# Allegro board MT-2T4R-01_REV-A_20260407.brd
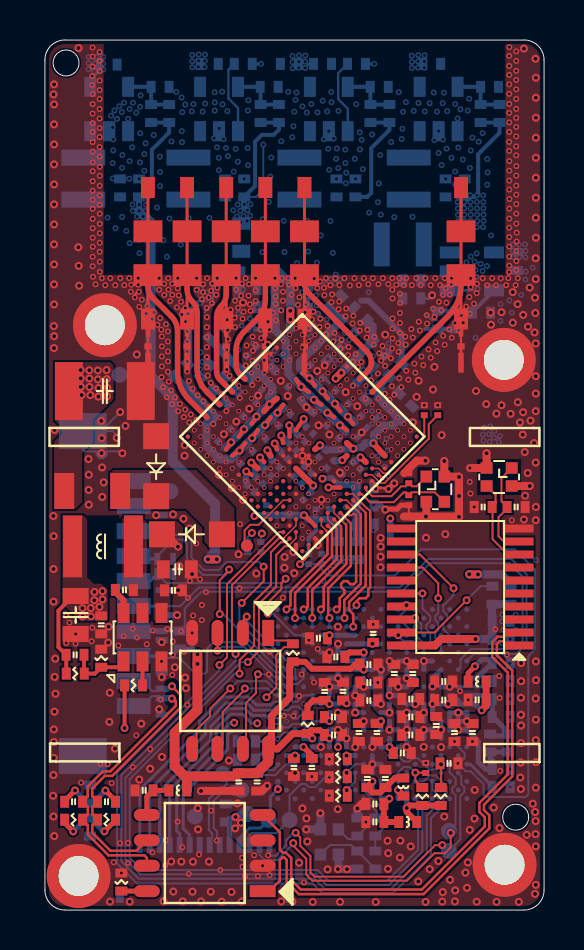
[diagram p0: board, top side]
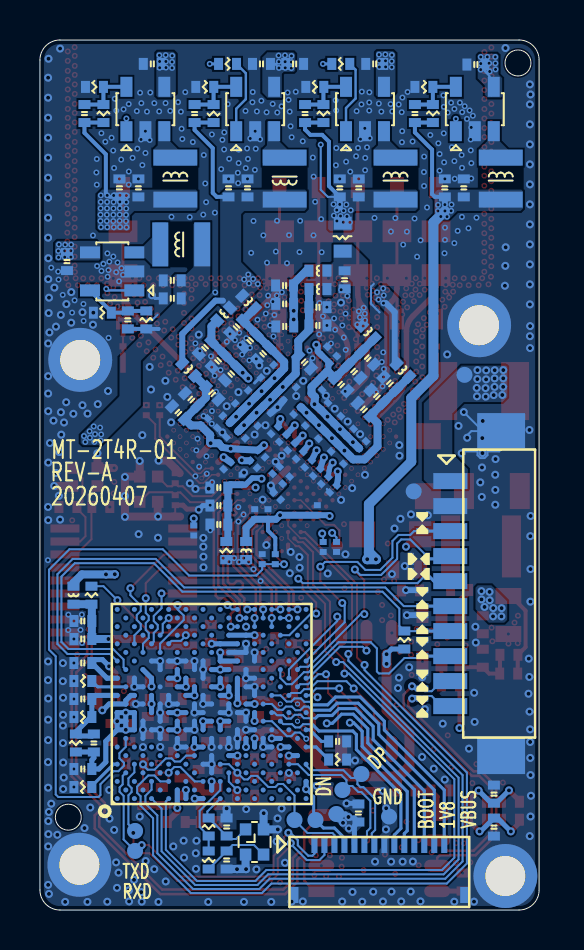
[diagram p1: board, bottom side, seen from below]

Outline 25 x 43.5 mm; copper layers: TOP, 02-GND1, 03-POWER, BOTTOM. Coordinates in mm from the lower left corner of the outline.
Outline path: circle c1.06,42.35 r0.65 ; circle c23.58,4.64 r0.65 ; 0,42.5 0,1 arc(0.29,0.29) 1,0 24,0 arc(24.71,0.29) 25,1 25,42.5 arc(24.71,43.21) 24,43.5 1,43.5 arc(0.29,43.21) 0,42.5

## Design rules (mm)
net group DP6: nets N2464554 N2465035
net group DP7: nets RXCAN TXCAN
net group DP8: nets CANH CANL
net group DP9: nets USB_DN USB_DP

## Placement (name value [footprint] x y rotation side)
C1  100pF  [0201]  13.12 27.08 225 bottom
C2  100pF  [0201]  14.39 25.81 225 bottom
C3  100pF  [0201]  13.76 26.45 225 bottom
C4  100pF  [0201]  15.05 25.16 225 bottom
C5  100pF  [0201]  15.67 24.54 225 bottom
C6  100pF  [0201]  12.34 26.3 45 bottom
C7  100pF  [0201]  12.98 25.67 45 bottom
C8  100pF  [0201]  13.62 25.03 45 bottom
C9  100pF  [0201]  14.27 24.38 45 bottom
C10  100pF  [0201]  14.89 23.76 45 bottom
C11  100pF  [0201]  11.53 24.4 135 bottom
C12  100pF  [0201]  12.12 24.96 135 bottom
C13  100pF  [0201]  9.62 22.49 135 bottom
C14  100pF  [0201]  10.88 23.74 135 bottom
C15  100pF  [0201]  10.24 23.1 135 bottom
C16  100pF  [0201]  11.04 25.83 315 bottom
C17  100pF  [0201]  10.75 25.19 315 bottom
C18  100pF  [0201]  10.1 24.52 315 bottom
C19  100pF  [0201]  9.46 23.88 315 bottom
C20  100pF  [0201]  8.84 23.26 315 bottom
C21  100pF  [0201]  10.31 27.52 315 bottom
C22  100pF  [0201]  10.79 27.99 315 bottom
C23  100pF  [0201]  11.14 21.89 135 bottom
C24  100pF  [0201]  11.99 22.73 135 bottom
C25  100pF  [0201]  12.84 23.58 135 bottom
C26  100pF  [0201]  10.31 21.05 135 bottom
C27  100pF  [0201]  17.3 18.98 90 bottom
C28  100pF  [0201]  15.62 22.21 135 bottom
C29  100pF  [0201]  11.57 22.31 135 bottom
C30  100pF  [0201]  12.41 23.16 135 bottom
C31  100pF  [0201]  14.3 22.29 45 bottom
C32  100pF  [0201]  13.24 23.99 135 bottom
C33  100pF  [0201]  10.73 21.48 135 bottom
C35  100pF  [0201]  15.84 23.47 315 bottom
C36  100pF  [0201]  13.9 22.81 45 bottom
C37  100pF  [0201]  16.77 24.4 315 bottom
C38  100pF  [0201]  16.3 23.93 315 bottom
C39  100pF  [0201]  14.87 21.51 270 bottom
C40  100pF  [0201]  13.17 21.99 315 bottom
C41  100pF  [0201]  12.67 21.49 315 bottom
C42  100pF  [0201]  13.12 20.69 45 bottom
C44  100pF  [0201]  14.24 19.79 270 bottom
C45  100pF  [0201]  11.11 19.99 270 bottom
C46  100pF  [0201]  13.58 19.79 270 bottom
C48  8pF  [0201]  18.23 21.59 270 top
C49  16pF  [0201]  18.23 20.49 90 top
C50  100pF  [0201]  19.67 24.99 270 top
C51  100nF  [0201]  13.87 17.54 270 bottom
C52  15pF  [C0402]  15.65 4.15 90 bottom
C53  15pF  [C0402]  15.65 2.5 270 bottom
C57  1uF  [C0402]  9.71 6.4 270 top
C66  10uF  [C0402]  11.08 30.14 0 bottom
C67  10nF  [C0402]  11.08 29.23 0 bottom
C68  100pF  [C0402]  11.75 27.39 45 bottom
C70  0.1uF  [C0402]  10.09 8.43 0 bottom
C72  10uF  [C0402]  8.58 27.59 45 bottom
C73  10nF  [C0402]  9.27 26.92 45 bottom
C74  100pF  [C0402]  9.92 26.27 45 bottom
C75  10uF  [C0402]  16.04 19.27 180 bottom
C76  10nF  [C0402]  16.04 20.22 180 bottom
C77  100pF  [C0402]  16.04 21.12 180 bottom
C81  10uF  [C0402]  12.74 29.18 180 bottom
C82  10nF  [C0402]  12.74 30.31 180 bottom
C83  100pF  [C0402]  12.75 31.22 180 bottom
C84  10uF  [C0402]  12.24 42.31 0 bottom
C85  0.1uF  [C0402]  13.9 42.31 180 bottom
C86  10pF  [C0402]  17.25 39.82 270 bottom
C87  10uF  [C0402]  14.6 36.11 90 bottom
C88  0.1uF  [C0402]  15.55 36.11 90 bottom
C90  10uF  [C0402]  15.15 29.15 135 bottom
C91  10nF  [C0402]  14.47 28.46 135 bottom
C92  100pF  [C0402]  13.82 27.81 135 bottom
C93  0.1uF  [C0402]  18.37 30.58 180 bottom
C94  10uF  [C0402]  18.37 31.48 180 bottom
C95  10uF  [C0402]  7.47 26.33 225 bottom
C96  10nF  [C0402]  8.12 25.68 225 bottom
C97  100pF  [C0402]  8.77 25.03 225 bottom
C98  10uF  [C0402]  16.37 25.83 45 bottom
C99  10nF  [C0402]  17.42 25.52 225 bottom
C100  100pF  [C0402]  18.07 24.87 225 bottom
C104  10uF  [C0402]  16.73 28.11 135 bottom
C105  10nF  [C0402]  16.08 27.46 135 bottom
C106  100pF  [C0402]  15.42 26.8 135 bottom
C116  0.1uF  [C0402]  9.74 31.51 270 bottom
C128  0.1uF  [C0402]  22.85 13.55 180 bottom
C129  10uF  [C0402]  22.85 14.45 180 bottom
C130  18pF  [C0402]  21.95 20.15 0 top
C131  18pF  [C0402]  23.6 20.15 180 top
C132  4.7nF  [C0402]  2.26 4.14 270 bottom
C133  47pF  [C0402]  1.44 5.41 0 top
C134  47pF  [C0402]  3.09 5.41 0 top
C135  47pF  [C0402]  2.26 5.79 90 bottom
C136  0.1uF  [C0402]  9.05 4.85 270 bottom
C137  0.1uF  [C0402]  4.97 5.98 0 top
C138  0.1uF  [C0402]  9.03 36.11 270 bottom
C139  0.1uF  [C0402]  4.72 36.11 270 bottom
C140  10pF  [C0402]  11.72 39.82 270 bottom
C141  10pF  [C0402]  6.22 39.82 270 bottom
C142  10uF  [C0402]  3.17 42.27 0 bottom
C143  10uF  [C0402]  3.77 36.11 270 bottom
C145  10uF  [C0402]  8.23 42.31 180 bottom
C146  10uF  [C0402]  9.98 36.11 270 bottom
C147  10uF  [C0402]  20.07 36.11 270 bottom
C148  10uF  [C0402]  19.37 42.31 0 bottom
C149  0.1uF  [C0402]  21.02 36.11 270 bottom
C150  10uF  [C0402]  23.65 32.42 270 bottom
C151  10pF  [C0402]  20.6 29.5 270 bottom
C153  10pF  [C0402]  22.77 39.82 270 bottom
C193  0.1uF  [C0402]  16.23 12.28 0 top
C194  1uF  [C0402]  21.65 10.51 180 top
C198  1uF  [C0402]  14.01 10.93 90 top
C200  0.1uF  [C0402]  22.85 12.35 0 bottom
C205  0.1uF  [C0402]  16.52 5.3 0 top
C206  10uF  [C0402]  16.23 10.47 0 top
C208  0.1uF  [C0402]  14.93 10.94 90 top
C209  10nF  [C0402]  16.23 11.38 0 top
C210  1uF  [C0402]  14.45 9.65 0 top
C214  10uF  [C0402]  19.6 9.22 270 top
C215  0.1uF  [C0402]  21.41 8.87 270 top
C216  10uF  [C0402]  18.32 10.55 0 top
C217  0.1uF  [C0402]  17.5 11.82 90 top
C220  0.1uF  [C0402]  16.15 6.58 270 top
C221  10nF  [C0402]  18.43 11.82 90 top
C223  1uF  [C0402]  22.85 7.05 0 bottom
C224  0.1uF  [C0402]  22.85 10.55 0 bottom
C225  0.1uF  [C0402]  22.3 8.35 90 bottom
C227  10nF  [C0402]  20.51 8.87 270 top
C229  0.1uF  [C0402]  17.9 7.85 0 top
C232  0.1uF  [C0402]  14.57 12.65 180 top
C234  0.1uF  [C0402]  13.37 7.12 270 top
C237  0.1uF  [C0402]  14.45 8.75 0 top
C244  0.1uF  [C0402]  12.47 7.12 270 top
C247  0.1uF  [C0402]  13.7 13.59 180 top
C249  0.1uF  [C0402]  16.44 13.83 270 top
C252  1uF  [C0402]  20.24 7.33 180 top
C253  100nF  [0201]  19.07 7.1 270 top
C254  0.1uF  [C0402]  10.63 6.4 270 top
C256  100pF  [C0402]  1.51 12.76 0 top
C257  22uF/10V  [C0805]  1.54 14.75 270 top
C258  10uF  [C0402]  2.82 14.26 270 top
C260  10uF/25V  [C0603]  6.63 17.03 0 top
C261  0.1uF  [C0402]  6.44 15.98 180 top
C263  0.1uF  [C0402]  3.98 16 180 top
C264  10uF  [C0402]  16.52 4.4 180 top
C265  10uF  [C0402]  17.05 6.58 90 top
C266  0.1uF  [C0402]  19.98 11.43 0 top
C267  10nF  [C0402]  19.98 10.5 0 top
C268  0.1uF  [C0402]  18.32 8.75 0 top
C269  10nF  [C0402]  18.32 9.65 0 top
C270  0.1uF  [C0402]  16.62 8.88 270 top
C271  10nF  [C0402]  15.72 8.88 270 top
C272  22uF/35V  [C1210]  3 25.95 180 top
D2  ESD  [SOD123_FL]  5.57 22.19 90 top
D3  S14  [SOD123_FL]  7.36 18.78 0 top
ESD15  -  [ESD0402]  5.85 10.17 270 bottom
ESD16  -  [ESD0402]  5.85 11.47 90 bottom
ESD17  -  [ESD0402]  5.85 13.09 90 bottom
ESD18  -  [ESD0402]  5.85 14.34 90 bottom
ESD19  -  [ESD0402]  5.85 15.59 90 bottom
ESD20  -  [ESD0402]  6.03 16.8 0 bottom
ESD21  -  [ESD0402]  6.03 17.56 0 bottom
ESD22  -  [ESD0402]  5.85 19.34 90 bottom
F1  SRF1206P100-24  [F1206]  2.37 20.95 0 top
FB1  BLM03AX100SZ1B  [L0402]  11.07 31.05 0 bottom
FB3  BLM03AX100SZ1B  [L0402]  8.55 28.9 225 bottom
FB5  BLM03AX100SZ1B  [L0402]  11.08 31.97 0 bottom
FB6  BLM03AX100SZ1B  [L0402]  14.67 17.97 90 bottom
FB7  BLM03AX100SZ1B  [L0402]  14.55 30.4 225 bottom
FB8  BLM03AX100SZ1B  [L0402]  6.82 26.98 225 bottom
FB9  BLM03AX100SZ1B  [L0402]  17.55 27.02 225 bottom
FB11  BLM03AX100SZ1B  [L0402]  15.8 29.8 315 bottom
FB12  BLM03AX100SZ1B  [L0402]  23.32 15.74 270 bottom
FB13  BLM03AX100SZ1B  [L0402]  6.66 5.98 180 top
FB16  BLM03AX100SZ1B  [L0402]  21.65 11.43 180 top
FB17  BLM03AX100SZ1B  [L0402]  18.18 4.4 0 top
FB18  BLM03AX100SZ1B  [L0402]  17.95 6.15 270 top
H1  M2  [MH3D2-2D0]  3 29.24 0 top
H2  M2  [MH3D2-2D0]  23.02 2.26 0 top
H3  M2  [MH3D2-2D0]  22.98 27.51 0 top
H4  M2  [MH3D2-2D0]  1.69 1.7 0 top
J2  MX1D25-10  [1D25T-10PLT]  4.45 15.82 270 bottom
J3  FPC-14_0D5  [HC-FPC-05-09-14RLTAG]  8 3.25 180 bottom
L2  FHD4020S-2R2MT  [L4020]  2.91 18.18 180 top
L5  FTC252012S2R2MBCA  [L2520]  12.74 36.57 270 bottom
L11  FTC252012S2R2MBCA  [L2520]  1.92 36.57 90 bottom
L12  FTC252012S2R2MBCA  [L2520]  7.19 36.57 90 bottom
L13  FTC252012S2R2MBCA  [L2520]  18.22 36.57 90 bottom
L14  FTC252012S2R2MBCA  [L2520]  17.92 33.28 0 bottom
R4  240/1%  [R0402]  22.85 11.45 0 bottom
R11  220K 1%  [R0402]  1.52 11.82 0 top
R12  30K 1%  [R0402]  2.82 12.59 90 top
R18  1M  [R0402]  16.55 4.15 270 bottom
R28  24K 1%  [0201]  19 24.99 270 top
R31  10K  [0201]  13.21 17.54 270 bottom
R40  133 1%  [R0402]  10.09 7.52 180 bottom
R48  5.1R  [R0402]  15.67 17.97 90 bottom
R50  100K  [R0402]  15.6 42.31 0 bottom
R51  47K 1%  [R0402]  16.3 39.82 90 bottom
R53  100K/1%  [R0402]  5.32 39.82 270 bottom
R54  33K 1%  [R0402]  16.74 41.16 0 bottom
R56  20K  [0201]  10.15 18.15 90 bottom
R57  20K  [0201]  10.81 18.15 90 bottom
R61  30K/1%  [R0402]  21.82 39.82 270 bottom
R63  49.9K/1%  [R0402]  22.27 41.16 180 bottom
R64  68K/1%  [R0402]  19.67 29.5 270 bottom
R67  68K/1%  [R0402]  21.87 29.87 180 bottom
R70  10K  [R0402]  22.42 15.74 270 bottom
R71  62R  [R0402]  1.44 4.51 0 top
R72  62R  [R0402]  3.09 4.51 0 top
R73  10K  [R0402]  3.83 1.4 90 top
R74  33K/1%  [R0402]  11.23 41.16 180 bottom
R75  68K/1%  [R0402]  10.8 39.82 270 bottom
R76  100K  [R0402]  9.93 42.31 180 bottom
R77  22K/1%  [R0402]  5.77 41.16 0 bottom
R83  0R  [R0603]  9.84 33.64 270 bottom
R86  10K/1%  [R0402]  22.85 9.65 180 bottom
R87  10K/1%  [R0402]  23.2 8.35 270 bottom
R89  1K  [R0402]  22.85 6.15 180 bottom
R90  1.8K  [R0402]  16.55 2.5 90 bottom
R93  100K  [R0402]  19.82 5.67 270 top
R94  100K  [R0402]  18.9 5.67 270 top
R97  100K  [R0402]  6.75 13.5 270 bottom
R98  10K  [R0402]  14.69 7.54 0 top
R99  10K  [R0402]  14.69 6.64 0 top
R100  10K  [R0402]  14.69 5.71 0 top
R101  0  [R0402]  13.16 9.27 270 top
R102  100K  [R0402]  4.44 11.23 0 top
R103  10K  [R0402]  12.42 12.86 90 top
RX1  ANTENNA  [MOTO_1X4_RF]  11.04 31.76 0 top
RX2  ANTENNA  [MOTO_1X4_RF]  9.08 31.76 0 top
RX3  ANTENNA  [MOTO_1X4_RF]  7.12 31.76 0 top
RX4  ANTENNA  [MOTO_1X4_RF]  5.16 31.76 0 top
TP14  NC  [TP_80]  3.74 26.76 270 bottom
TP28  T  [TP_60]  10.12 18.22 45 top
TP31  NC  [TP_80]  6.28 20.93 0 bottom
TP36  NC  [TP_80]  12.25 4.5 180 bottom
TP37  NC  [TP_80]  20.24 2.95 180 bottom
TP38  NC  [TP_80]  20.24 3.95 180 bottom
TP39  NC  [TP_80]  10.15 4.8 180 bottom
TP40  NC  [TP_80]  9.85 6 225 bottom
TP41  NC  [TP_80]  8.9 6.8 135 bottom
TP42  NC  [TP_80]  7.51 4.67 180 bottom
TP43  NC  [TP_80]  11.2 4.5 180 bottom
TX2  ANTENNA  [MOTO_1X4_RF]  13 31.76 0 top
TX3  ANTENNA  [MOTO_1X4_RF]  20.84 31.76 0 top
U1  Cheetah_4T4R  [CHEETAH_WLCSP265]  12.89 23.67 315 top
U4  SY8105IADC  [SOT23-6]  4.89 13.63 90 top
U8  YX55015F  [SOT23-5L]  3.22 40.04 90 bottom
U10  YX55015F  [SOT23-5L]  14.22 40.04 90 bottom
U11  YX55015F  [SOT23-5L]  21.37 31.93 0 bottom
U12  SIT1042AT/3  [SOP-8]  8 2.85 90 top
U14  MCP2515  [TSSOP20]  20.8 16.15 180 top
U15  YX55015F  [SOT23-5L]  8.72 40.04 90 bottom
U16  YX55015F  [SOT23-5L]  19.72 40.04 90 bottom
U19  XT25F16FSOIGU-S  [SOP-8]  9.28 10.95 180 top
U21  X2100L  [X2100_BGA264_0D43_10X10]  16.4 10.3 90 bottom
Y1  40MHz  [CRY4_2016]  19.55 21.04 270 top
Y2  16M  [CRY4_2016]  22.75 21.65 180 top
Y4  24M_20PPM  [CRY4_2016]  14.25 3.4 270 bottom

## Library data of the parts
C1-C33 C35-C42 C44-C46 C48-C51 C66-C68 C72-C77 C81-C86 C90-C92 C95-C100 C104-C106 C210 C223 C256 C257 = CAP NP
C52 C53 = CAP_NP_MINI
C57 C70 C87 C88 C116 C193 C194 C198 C200 C205 C206 C208 C209 C214-C217 C220 C221 C224 C225 C227 C229 C232 C234 C237 C244 C247 C249 C254 C258 C260 C264-C271 = CAP_NP
C93 C94 C128 C129 C133 C134 C136-C140 C142 C143 C145-C150 C261 C263 C272 = CAP_NP_3
C130-C132 C135 = CAP_NP_2
C141 C151 C153 C252 C253 = CAP NP_2
D2 = Diode H Zener_0
D3 = DIODE PIN_5
ESD15-ESD22 = 1_0.5KE100A
F1 = FUSE
FB1 FB3 FB5-FB9 FB11-FB13 FB16-FB18 = FB
H1-H4 = HOLE-V8_3
J2 = CON12_0
J3 = CON16_0
L2 L11-L14 = INDUCTOR
L5 = Inductor 1206 H_0
R4 R40 = R_10
R11 R12 = R_0
R18 R103 = R_MINI_7
R28 R48 R50 R56 R57 = RES_0
R31 R51 R54 R83 = R
R53 R61 R63 R64 R67 R70-R77 R86 R87 R93 R94 R97 R101 R102 = R_MINI
R89 = R_1
R90 R98-R100 = R_52
RX1-RX4 TX2 TX3 = ANTENNA_2
TP14 TP31 TP36-TP43 = TEST_0
TP28 = TEST_2
U1 = Cheetah_4T4R
U4 = SOT-26_2
U8 U10 U11 U15 U16 = DCDC_RT8096C_6
U12 = IC-8_1
U14 = SIT2515_1
U19 = XM25QH128A_0
U21 = X2100L
Y1 Y2 Y4 = CRYSTAL_4

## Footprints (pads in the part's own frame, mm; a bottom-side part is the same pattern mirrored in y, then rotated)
1D25T-10PLT
  rect 0.8x1.7 smd: 1(-5.625,0) 2(-4.375,0) 3(-3.125,0) 4(-1.875,0) 5(-0.625,0) 6(0.625,0) 7(1.875,0) 8(3.125,0) 9(4.375,0) 10(5.625,0)
  rect 1.8x2.4 smd: 11(-8.125,2.55) 12(8.125,2.55)
0201
  rect 0.3x0.35 smd: 1(-0.25,0) 2(0.25,0)
C0402
  rect 0.45x0.599 smd: 1(-0.45,0) 2(0.45,0)
C0603
  rect 0.65x0.899 smd: 1(-0.7,0) 2(0.7,0)
C0805
  rect 0.8x1.3 smd: 1(-0.95,0) 2(0.95,0)
C1210
  rect 1.4x2.9 smd: 1(-1.8,0) 2(1.8,0)
CHEETAH_WLCSP265
  round 0.221 smd: A1(-4.05,4.05) A2(-3.6,4.05) A3(-3.15,4.05) A4(-2.7,4.05) A5(-2.25,4.05) A6(-1.8,4.05) A7(-1.35,4.05) A8(-0.9,4.05) A9(-0.45,4.05) A10(0,4.05) A11(0.45,4.05) A12(0.9,4.05) A13(1.35,4.05) A14(1.8,4.05) A15(2.25,4.05) A16(2.7,4.05) A17(3.15,4.05) A18(3.6,4.05) A19(4.05,4.05) B1(-4.05,3.6) B2(-3.6,3.6) B3(-3.15,3.6) B4(-2.7,3.6) B5(-2.25,3.6) B7(-1.35,3.6) B9(-0.45,3.6) B11(0.45,3.6) B13(1.35,3.6) B14(1.8,3.6) B15(2.25,3.6) B16(2.7,3.6) B17(3.15,3.6) B18(3.6,3.6) B19(4.05,3.6) C1(-4.05,3.15) C2(-3.6,3.15) C3(-3.15,3.15) C5(-2.25,3.15) C7(-1.35,3.15) C9(-0.45,3.15) C11(0.45,3.15) C13(1.35,3.15) C14(1.8,3.15) C15(2.25,3.15) C16(2.7,3.15) C17(3.15,3.15) C18(3.6,3.15) C19(4.05,3.15) D1(-4.05,2.7) D2(-3.6,2.7) D3(-3.15,2.7) D5(-2.25,2.7) D7(-1.35,2.7) D9(-0.45,2.7) D11(0.45,2.7) D13(1.35,2.7) D16(2.7,2.7) D17(3.15,2.7) D18(3.6,2.7) D19(4.05,2.7) E1(-4.05,2.25) E2(-3.6,2.25) E3(-3.15,2.25) E5(-2.25,2.25) E7(-1.35,2.25) E9(-0.45,2.25) E11(0.45,2.25) E13(1.35,2.25) E17(3.15,2.25) E18(3.6,2.25) E19(4.05,2.25) F1(-4.05,1.8) F2(-3.6,1.8) F3(-3.15,1.8) F5(-2.25,1.8) F7(-1.35,1.8) F9(-0.45,1.8) F11(0.45,1.8) F13(1.35,1.8) F14(1.8,1.8) F17(3.15,1.8) F18(3.6,1.8) F19(4.05,1.8) G1(-4.05,1.35) G2(-3.6,1.35) G3(-3.15,1.35) G5(-2.25,1.35) G7(-1.35,1.35) G9(-0.45,1.35) G11(0.45,1.35) G13(1.35,1.35) G14(1.8,1.35) G17(3.15,1.35) G18(3.6,1.35) G19(4.05,1.35) H1(-4.05,0.9) H2(-3.6,0.9) H3(-3.15,0.9) H13(1.35,0.9) H14(1.8,0.9) H15(2.25,0.9) H16(2.7,0.9) H17(3.15,0.9) H18(3.6,0.9) H19(4.05,0.9) J1(-4.05,0.45) J2(-3.6,0.45) J3(-3.15,0.45) J4(-2.7,0.45) J5(-2.25,0.45) J6(-1.8,0.45) J7(-1.35,0.45) J16(2.7,0.45) J17(3.15,0.45) J18(3.6,0.45) J19(4.05,0.45) K1(-4.05,0) K9(-0.45,0) K10(0,0) K11(0.45,0) K12(0.9,0) K16(2.7,0) K17(3.15,0) K18(3.6,0) K19(4.05,0) L1(-4.05,-0.45) L2(-3.6,-0.45) L3(-3.15,-0.45) L4(-2.7,-0.45) L5(-2.25,-0.45) L6(-1.8,-0.45) L7(-1.35,-0.45) L9(-0.45,-0.45) L10(0,-0.45) L11(0.45,-0.45) L12(0.9,-0.45) L13(1.35,-0.45) L14(1.8,-0.45) L16(2.7,-0.45) L17(3.15,-0.45) L18(3.6,-0.45) L19(4.05,-0.45) M1(-4.05,-0.9) M9(-0.45,-0.9) M10(0,-0.9) M11(0.45,-0.9) M12(0.9,-0.9) M13(1.35,-0.9) M14(1.8,-0.9) M17(3.15,-0.9) M18(3.6,-0.9) M19(4.05,-0.9) N1(-4.05,-1.35) N2(-3.6,-1.35) N3(-3.15,-1.35) N4(-2.7,-1.35) N5(-2.25,-1.35) N6(-1.8,-1.35) N7(-1.35,-1.35) N9(-0.45,-1.35) N10(0,-1.35) N11(0.45,-1.35) N12(0.9,-1.35) N13(1.35,-1.35) N14(1.8,-1.35) N17(3.15,-1.35) N18(3.6,-1.35) N19(4.05,-1.35) P1(-4.05,-1.8) P9(-0.45,-1.8) P10(0,-1.8) P11(0.45,-1.8) P12(0.9,-1.8) P13(1.35,-1.8) P14(1.8,-1.8) P15(2.25,-1.8) P16(2.7,-1.8) P17(3.15,-1.8) P18(3.6,-1.8) P19(4.05,-1.8) R1(-4.05,-2.25) R2(-3.6,-2.25) R3(-3.15,-2.25) R4(-2.7,-2.25) R5(-2.25,-2.25) R6(-1.8,-2.25) R7(-1.35,-2.25) R9(-0.45,-2.25) R10(0,-2.25) R11(0.45,-2.25) R12(0.9,-2.25) R13(1.35,-2.25) R14(1.8,-2.25) R15(2.25,-2.25) R16(2.7,-2.25) R17(3.15,-2.25) R18(3.6,-2.25) R19(4.05,-2.25) T1(-4.05,-2.7) T9(-0.45,-2.7) T10(0,-2.7) T11(0.45,-2.7) T12(0.9,-2.7) T13(1.35,-2.7) T14(1.8,-2.7) T15(2.25,-2.7) T17(3.15,-2.7) T18(3.6,-2.7) T19(4.05,-2.7) U1(-4.05,-3.15) U2(-3.6,-3.15) U3(-3.15,-3.15) U4(-2.7,-3.15) U5(-2.25,-3.15) U6(-1.8,-3.15) U7(-1.35,-3.15) U9(-0.45,-3.15) U10(0,-3.15) U11(0.45,-3.15) U12(0.9,-3.15) U13(1.35,-3.15) U14(1.8,-3.15) U15(2.25,-3.15) U16(2.7,-3.15) U17(3.15,-3.15) U18(3.6,-3.15) U19(4.05,-3.15) V1(-4.05,-3.6) V2(-3.6,-3.6) V3(-3.15,-3.6) V4(-2.7,-3.6) V5(-2.25,-3.6) V6(-1.8,-3.6) V7(-1.35,-3.6) V8(-0.9,-3.6) V9(-0.45,-3.6) V10(0,-3.6) V11(0.45,-3.6) V12(0.9,-3.6) V13(1.35,-3.6) V14(1.8,-3.6) V15(2.25,-3.6) V16(2.7,-3.6) V17(3.15,-3.6) V18(3.6,-3.6) V19(4.05,-3.6) W1(-4.05,-4.05) W2(-3.6,-4.05) W3(-3.15,-4.05) W4(-2.7,-4.05) W5(-2.25,-4.05) W6(-1.8,-4.05) W7(-1.35,-4.05) W8(-0.9,-4.05) W9(-0.45,-4.05) W10(0,-4.05) W11(0.45,-4.05) W12(0.9,-4.05) W13(1.35,-4.05) W14(1.8,-4.05) W15(2.25,-4.05) W16(2.7,-4.05) W17(3.15,-4.05) W18(3.6,-4.05) W19(4.05,-4.05)
CRY4_2016
  rect 0.6x0.58 smd: 1(-0.63,-0.45) 2(0.63,-0.45) 3(0.63,0.45) 4(-0.63,0.45)
ESD0402
  rect 0.3x0.599 smd: 1(-0.399,0) 2(0.399,0)
F1206
  rect 1x1.8 smd: 1(-1.4,0) 2(1.4,0)
HC-FPC-05-09-14RLTAG
  rect 0.3x0.8 smd: 1(-3.25,0) 2(-2.75,0) 3(-2.25,0) 4(-1.75,0) 5(-1.25,0) 6(-0.75,0) 7(-0.25,0) 8(0.25,0) 9(0.75,0) 10(1.25,0) 11(1.75,0) 12(2.25,0) 13(2.75,0) 14(3.25,0)
  rect 0.4x0.8 smd: 15(-4.25,-2.5) 16(4.25,-2.5)
L0402
  rect 0.45x0.599 smd: 1(-0.45,0) 2(0.45,0)
L2520
  rect 0.8x2.2 smd: 1(-1.05,0) 2(1.05,0)
L4020
  rect 0.95x3.1 smd: 1(-1.525,0) 2(1.525,0)
MH3D2-2D0
  round 3.2 hole 2: 1(0,0)
MOTO_1X4_RF
  custom 0.36x0.36 smd: 1(0,0)
R0402
  rect 0.45x0.599 smd: 1(-0.45,0) 2(0.45,0)
R0603
  rect 0.65x0.899 smd: 1(-0.7,0) 2(0.7,0)
SOD123_FL
  rect 1.3x1.3 smd: 1(-1.5,0) 2(1.5,0)
SOP-8
  rect 0.6x1.3 smd: 1(-1.905,-2.9)
  oval 0.6x1.3 smd: 2(-0.635,-2.9) 3(0.635,-2.9) 4(1.905,-2.9) 5(1.905,2.9) 6(0.635,2.9) 7(-0.635,2.9) 8(-1.905,2.9)
SOT23-5L
  rect 1x0.6 smd: 1(-1.1,0.95) 2(-1.1,0) 3(-1.1,-0.95) 4(1.12,-0.95) 5(1.12,0.95)
SOT23-6
  rect 1x0.6 smd: 1(-1.2,0.95) 2(-1.2,0) 3(-1.2,-0.95) 4(1.22,-0.95) 5(1.22,0) 6(1.22,0.95)
TP_60
  round 0.6 smd: 1(0,0)
TP_80
  round 0.8 smd: 1(0,0)
TSSOP20
  rect 1.45x0.4 smd: 1(-2.95,2.925) 2(-2.95,2.275) 3(-2.95,1.625) 4(-2.95,0.975) 5(-2.95,0.325) 6(-2.95,-0.325) 7(-2.95,-0.975) 8(-2.95,-1.625) 9(-2.95,-2.275) 10(-2.95,-2.925) 11(2.95,-2.925) 12(2.95,-2.275) 13(2.95,-1.625) 14(2.95,-0.975) 15(2.95,-0.325) 16(2.95,0.325) 17(2.95,0.975) 18(2.95,1.625) 19(2.95,2.275) 20(2.95,2.925)
X2100_BGA264_0D43_10X10
  round 0.25 smd: A1(-4.73,4.73) A3(-3.87,4.73) A5(-3.01,4.73) A7(-2.15,4.73) A9(-1.29,4.73) A11(-0.43,4.73) A13(0.43,4.73) A15(1.29,4.73) A17(2.15,4.73) A19(3.01,4.73) A21(3.87,4.73) A23(4.73,4.73) AA1(-4.73,-3.87) AA3(-3.87,-3.87) AA5(-3.01,-3.87) AA7(-2.15,-3.87) AA9(-1.29,-3.87) AA11(-0.43,-3.87) AA13(0.43,-3.87) AA15(1.29,-3.87) AA17(2.15,-3.87) AA19(3.01,-3.87) AA21(3.87,-3.87) AA23(4.73,-3.87) AB2(-4.3,-4.3) AB4(-3.44,-4.3) AB6(-2.58,-4.3) AB8(-1.72,-4.3) AB10(-0.86,-4.3) AB12(0,-4.3) AB14(0.86,-4.3) AB16(1.72,-4.3) AB18(2.58,-4.3) AB20(3.44,-4.3) AB22(4.3,-4.3) AC1(-4.73,-4.73) AC3(-3.87,-4.73) AC5(-3.01,-4.73) AC7(-2.15,-4.73) AC9(-1.29,-4.73) AC11(-0.43,-4.73) AC13(0.43,-4.73) AC15(1.29,-4.73) AC17(2.15,-4.73) AC19(3.01,-4.73) AC21(3.87,-4.73) AC23(4.73,-4.73) B2(-4.3,4.3) B4(-3.44,4.3) B6(-2.58,4.3) B8(-1.72,4.3) B10(-0.86,4.3) B12(0,4.3) B14(0.86,4.3) B16(1.72,4.3) B18(2.58,4.3) B20(3.44,4.3) B22(4.3,4.3) C1(-4.73,3.87) C3(-3.87,3.87) C5(-3.01,3.87) C7(-2.15,3.87) C9(-1.29,3.87) C11(-0.43,3.87) C13(0.43,3.87) C15(1.29,3.87) C17(2.15,3.87) C19(3.01,3.87) C21(3.87,3.87) C23(4.73,3.87) D2(-4.3,3.44) D4(-3.44,3.44) D6(-2.58,3.44) D8(-1.72,3.44) D10(-0.86,3.44) D12(0,3.44) D14(0.86,3.44) D16(1.72,3.44) D18(2.58,3.44) D20(3.44,3.44) D22(4.3,3.44) E1(-4.73,3.01) E3(-3.87,3.01) E5(-3.01,3.01) E7(-2.15,3.01) E9(-1.29,3.01) E11(-0.43,3.01) E13(0.43,3.01) E15(1.29,3.01) E17(2.15,3.01) E19(3.01,3.01) E21(3.87,3.01) E23(4.73,3.01) F2(-4.3,2.58) F4(-3.44,2.58) F6(-2.58,2.58) F8(-1.72,2.58) F10(-0.86,2.58) F12(0,2.58) F14(0.86,2.58) F16(1.72,2.58) F18(2.58,2.58) F20(3.44,2.58) F22(4.3,2.58) G1(-4.73,2.15) G3(-3.87,2.15) G5(-3.01,2.15) G9(-1.29,2.15) G11(-0.43,2.15) G13(0.43,2.15) G15(1.29,2.15) G17(2.15,2.15) G19(3.01,2.15) G21(3.87,2.15) G23(4.73,2.15) H2(-4.3,1.72) H4(-3.44,1.72) H6(-2.58,1.72) H8(-1.72,1.72) H10(-0.86,1.72) H12(0,1.72) H14(0.86,1.72) H16(1.72,1.72) H18(2.58,1.72) H20(3.44,1.72) H22(4.3,1.72) J1(-4.73,1.29) J3(-3.87,1.29) J5(-3.01,1.29) J7(-2.15,1.29) J9(-1.29,1.29) J11(-0.43,1.29) J13(0.43,1.29) J15(1.29,1.29) J17(2.15,1.29) J19(3.01,1.29) J21(3.87,1.29) J23(4.73,1.29) K2(-4.3,0.86) K4(-3.44,0.86) K6(-2.58,0.86) K8(-1.72,0.86) K10(-0.86,0.86) K12(0,0.86) K14(0.86,0.86) K16(1.72,0.86) K18(2.58,0.86) K20(3.44,0.86) K22(4.3,0.86) L1(-4.73,0.43) L3(-3.87,0.43) L5(-3.01,0.43) L7(-2.15,0.43) L9(-1.29,0.43) L11(-0.43,0.43) L13(0.43,0.43) L15(1.29,0.43) L17(2.15,0.43) L19(3.01,0.43) L21(3.87,0.43) L23(4.73,0.43) M2(-4.3,0) M4(-3.44,0) M6(-2.58,0) M8(-1.72,0) M10(-0.86,0) M12(0,0) M14(0.86,0) M16(1.72,0) M18(2.58,0) M20(3.44,0) M22(4.3,0) N1(-4.73,-0.43) N3(-3.87,-0.43) N5(-3.01,-0.43) N7(-2.15,-0.43) N9(-1.29,-0.43) N11(-0.43,-0.43) N13(0.43,-0.43) N15(1.29,-0.43) N17(2.15,-0.43) N19(3.01,-0.43) N21(3.87,-0.43) N23(4.73,-0.43) P2(-4.3,-0.86) P4(-3.44,-0.86) P6(-2.58,-0.86) P8(-1.72,-0.86) P10(-0.86,-0.86) P12(0,-0.86) P14(0.86,-0.86) P16(1.72,-0.86) P18(2.58,-0.86) P20(3.44,-0.86) P22(4.3,-0.86) R1(-4.73,-1.29) R3(-3.87,-1.29) R5(-3.01,-1.29) R7(-2.15,-1.29) R9(-1.29,-1.29) R11(-0.43,-1.29) R13(0.43,-1.29) R15(1.29,-1.29) R17(2.15,-1.29) R19(3.01,-1.29) R21(3.87,-1.29) R23(4.73,-1.29) T2(-4.3,-1.72) T4(-3.44,-1.72) T6(-2.58,-1.72) T8(-1.72,-1.72) T10(-0.86,-1.72) T12(0,-1.72) T14(0.86,-1.72) T16(1.72,-1.72) T18(2.58,-1.72) T20(3.44,-1.72) T22(4.3,-1.72) U1(-4.73,-2.15) U3(-3.87,-2.15) U5(-3.01,-2.15) U7(-2.15,-2.15) U9(-1.29,-2.15) U11(-0.43,-2.15) U13(0.43,-2.15) U15(1.29,-2.15) U17(2.15,-2.15) U19(3.01,-2.15) U21(3.87,-2.15) U23(4.73,-2.15) V2(-4.3,-2.58) V4(-3.44,-2.58) V6(-2.58,-2.58) V8(-1.72,-2.58) V10(-0.86,-2.58) V12(0,-2.58) V14(0.86,-2.58) V16(1.72,-2.58) V18(2.58,-2.58) V20(3.44,-2.58) V22(4.3,-2.58) W1(-4.73,-3.01) W3(-3.87,-3.01) W5(-3.01,-3.01) W7(-2.15,-3.01) W9(-1.29,-3.01) W11(-0.43,-3.01) W13(0.43,-3.01) W15(1.29,-3.01) W17(2.15,-3.01) W19(3.01,-3.01) W21(3.87,-3.01) W23(4.73,-3.01) Y2(-4.3,-3.44) Y4(-3.44,-3.44) Y6(-2.58,-3.44) Y8(-1.72,-3.44) Y10(-0.86,-3.44) Y12(0,-3.44) Y14(0.86,-3.44) Y16(1.72,-3.44) Y18(2.58,-3.44) Y20(3.44,-3.44) Y22(4.3,-3.44)

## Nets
AVDD14_RX: C11.2 C12.2 C13.2 C14.2 C15.2 C95.2 C96.2 C97.2 FB8.2 U1.J6(AVDD14_B) U1.L6(AVDD14_RX1) U1.N6(AVDD14_RX2) U1.R6(AVDD14_RX3) U1.U6(AVDD14_RX4)
AVDD14_SX: C35.2 C36.2 C37.2 C38.2 C98.2 C99.2 C100.2 FB9.2 U1.E17(AVDD14_SX1) U1.E18(AVDD14_SX2) U1.G14(AVDD14_SX3) U1.K12(AVDD14_LO)
AVDD14_TX: C1.2 C2.2 C3.2 C4.2 C5.2 C90.2 C91.2 C92.2 FB7.2 U1.E5(AVDD14_TX1) U1.E7(AVDD14_TX2) U1.E9(AVDD14_TX3) U1.E11(AVDD14_TX4) U1.E13(AVDD14_TX5)
AVDD18_RX: C16.2 C17.2 C18.2 C19.2 C20.2 C21.2 C22.2 C72.2 C73.2 C74.2 FB3.2 U1.E2(AVDD18_B1) U1.F2(AVDD18_B2) U1.J5(AVDD18_RX1) U1.L5(AVDD18_RX2) U1.N5(AVDD18_RX3) U1.R5(AVDD18_RX4) U1.U5(AVDD18_RX5)
AVDD18_TX: C6.2 C7.2 C8.2 C9.2 C10.2 C66.2 C67.2 C68.2 FB1.2 U1.F5(AVDD18_TX1) U1.F7(AVDD18_TX2) U1.F9(AVDD18_TX3) U1.F11(AVDD18_TX4) U1.F13(AVDD18_TX5)
AVDD18_XO: C39.2 C75.2 C76.2 C77.2 R48.2 U1.K17(AVDD18_XO)
DVDD14: C23.2 C24.2 C25.2 C26.2 C27.2 C40.2 C41.2 C42.2 C104.2 C105.2 C106.2 FB11.2 U1.K18(AVDD14_BBPLL) U1.L9(AVDD14_AD1) U1.N9(AVDD14_AD2) U1.N12(DVDD14_1) U1.N13(DVDD14_2) U1.N14(DVDD14_3) U1.R9(AVDD14_AD3) U1.U9(AVDD14_AD4)
DVDD18: C28.2 C29.2 C30.2 C31.2 C32.2 C33.2 C81.2 C82.2 C83.2 FB5.2 U1.G17(AVDD18_GPADC) U1.H15(AVDD18_BG) U1.K9(AVDD18_AD1) U1.L17(DVDD18) U1.M9(AVDD18_AD2) U1.P9(AVDD18_AD3) U1.P13(AVDD18_TOP) U1.T9(AVDD18_AD4)
DVDD_GPIO: C44.2 C45.2 C46.2 FB6.2 R31.1 U1.T17(DVDD_GPIO1) U1.T18(DVDD_GPIO2) U1.U11(DVDD_GPIO3)
GND: C1.1 C2.1 C3.1 C4.1 C5.1 C6.1 C7.1 C8.1 C9.1 C10.1 C11.1 C12.1 C13.1 C14.1 C15.1 C16.1 C17.1 C18.1 C19.1 C20.1 C21.1 C22.1 C23.1 C24.1 C25.1 C26.1 C27.1 C28.1 C29.1 C30.1 C31.1 C32.1 C33.1 C35.1 C36.1 C37.1 C38.1 C39.1 C40.1 C41.1 C42.1 C44.1 C45.1 C46.1 C48.1 C49.1 C50.1 C51.1 C52.2 C53.2 C57.2 C66.1 C67.1 C68.1 C70.1 C72.1 C73.1 C74.1 C75.1 C76.1 C77.1 C81.1 C82.1 C83.1 C84.1 C85.1 C87.2 C88.2 C90.1 C91.1 C92.1 C93.1 C94.1 C95.1 C96.1 C97.1 C98.1 C99.1 C100.1 C104.1 C105.1 C106.1 C116.2 C128.1 C129.1 C130.1 C131.1 C132.2 C135.2 C136.1 C137.1 C138.1 C139.1 C142.2 C143.1 C145.1 C146.1 C147.1 C148.2 C149.1 C150.2 C193.2 C194.2 C198.2 C200.2 C205.1 C206.2 C208.2 C209.2 C210.2 C214.2 C215.2 C216.2 C217.2 C220.1 C221.2 C223.2 C224.2 C227.2 C229.2 C232.2 C234.2 C237.2 C244.2 C247.2 C249.1 C252.1 C253.1 C254.2 C257.2 C258.2 C260.2 C261.1 C264.2 C265.2 C266.2 C267.2 C268.2 C269.2 C270.2 C271.2 C272.1 D2.2 ESD15.2(CATHODE) ESD16.2(CATHODE) ESD17.2(CATHODE) ESD18.2(CATHODE) ESD19.2(CATHODE) ESD20.2(CATHODE) ESD21.2(CATHODE) ESD22.2(CATHODE) H1.1 H2.1 H3.1 H4.1 J2.2 J2.11 J2.12 J3.8 J3.15 J3.16 R4.2 R12.2 R28.1 R40.2 R54.2 R56.1 R57.1 R63.1 R67.1 R73.2 R74.1 R77.2 R86.1 R89.1 R98.1 R99.1 R100.1 TP31.1(A) TP42.1(A) U1.A2(G_AVSS_RF1) U1.A3(G_AVSS_RF2) U1.A4(G_AVSS_RF3) U1.A5(G_AVSS_RF4) U1.A6(TX4) U1.A7(G_AVSS_RF5) U1.A8(TX3) U1.A9(G_AVSS_RF6) U1.A11(G_AVSS_RF7) U1.A13(G_AVSS_RF8) U1.A14(G_AVSS_RF9) U1.A15(G_AVSS_RF10) U1.A16(LO_SYNCI) U1.A17(G_AVSS_RF11) U1.A18(G_AVSS_RF12) U1.B1(G_AVSS_RF13) U1.B2(G_AVSS_RF14) U1.B3(G_AVSS_RF15) U1.B4(G_AVSS_RF16) U1.B5(G_AVSS_RF17) U1.B7(G_AVSS_RF18) U1.B9(G_AVSS_RF19) U1.B11(G_AVSS_RF20) U1.B13(G_AVSS_RF21) U1.B14(G_AVSS_RF22) U1.B15(G_AVSS_RF23) U1.B16(G_AVSS_RF24) U1.B17(G_AVSS_RF25) U1.B18(G_AVSS_RF26) U1.B19(G_AVSS_RF27) U1.C1(G_AVSS_RF28) U1.C2(LO_SYNCO2) U1.C3(G_AVSS_RF29) U1.C5(G_AVSS_RF30) U1.C7(G_AVSS_RF31) U1.C9(G_AVSS_RF32) U1.C11(G_AVSS_RF33) U1.C13(G_AVSS_RF34) U1.C14(G_AVSS_RF35) U1.C15(G_AVSS_RF36) U1.C16(G_AVSS_RF37) U1.C17(G_AVSS_RF38) U1.C18(G_AVSS_RF39) U1.C19(LO_SYNCO) U1.D1(G_AVSS_RF40) U1.D2(G_AVSS_RF41) U1.D3(G_AVSS_RF42) U1.D5(G_AVSS_RF43) U1.D7(G_AVSS_RF44) U1.D9(G_AVSS_RF45) U1.D11(G_AVSS_RF46) U1.D13(G_AVSS_RF47) U1.D16(G_AVSS_RF48) U1.D17(G_AVSS_RF49) U1.D18(G_AVSS_RF50) U1.D19(G_AVSS_RF51) U1.E1(G_AVSS_RF52) U1.E3(G_AVSS_RF53) U1.E19(ACT_SX) U1.F1(G_AVSS_RF54) U1.F3(G_AVSS_RF55) U1.F14(G_AVSS_RF56) U1.F17(G_AVSS_RF57) U1.F18(G_AVSS_RF58) U1.F19(G_AVSS_RF59) U1.G1(G_AVSS_RF60) U1.G2(G_AVSS_RF61) U1.G3(G_AVSS_RF62) U1.G5(G_AVSS_RF63) U1.G7(G_AVSS_RF64) U1.G9(G_AVSS_RF65) U1.G11(G_AVSS_RF66) U1.G13(G_AVSS_RF67) U1.G19(G_AVSS43) U1.H1(G_AVSS_RF68) U1.H2(G_AVSS_RF69) U1.H3(G_AVSS_RF70) U1.H13(G_AVSS_RF71) U1.H14(G_AVSS42) U1.H16(G_AVSS41) U1.H17(G_AVSS40) U1.H19(ACT_BBPLL) U1.J1(G_AVSS_RF72) U1.J2(G_AVSS_RF73) U1.J3(G_AVSS_RF74) U1.J4(G_AVSS_RF75) U1.J7(G_AVSS_RF76) U1.J16(G_AVSS39) U1.J17(G_AVSS38) U1.J18(XTAL_SYNCI) U1.K10(G_AVSS37) U1.K11(G_AVSS_RF77) U1.K16(XTAL_SYNCO) U1.L1(G_AVSS_RF112) U1.L2(G_AVSS_RF111) U1.L3(G_AVSS_RF110) U1.L4(G_AVSS_RF109) U1.L7(G_AVSS_RF108) U1.L10(G_AVSS36) U1.L11(G_AVSS_RF107) U1.L12(G_AVSS_RF106) U1.L13(G_DVSS25) U1.L14(G_AVSS35) U1.L16(G_AVSS34) U1.M10(G_AVSS33) U1.M11(G_DVSS24) U1.M12(G_DVSS23) U1.M13(G_DVSS22) U1.M14(G_DVSS21) U1.M17(G_DVSS20) U1.N1(G_AVSS_RF105) U1.N2(G_AVSS_RF104) U1.N3(G_AVSS_RF103) U1.N4(G_AVSS_RF102) U1.N7(G_AVSS_RF101) U1.N10(G_AVSS32) U1.N11(G_DVSS19) U1.N17(G_DVSS18) U1.P10(G_AVSS31) U1.P11(G_DVSS17) U1.P12(G_DVSS16) U1.P16(G_DVSS15) U1.P17(G_DVSS14) U1.R1(G_AVSS_RF100) U1.R2(G_AVSS_RF99) U1.R3(G_AVSS_RF98) U1.R4(G_AVSS_RF97) U1.R7(G_AVSS_RF96) U1.R10(G_AVSS30) U1.R11(G_DVSS13) U1.R14(G_AVSS29) U1.R15(ACT_32K) U1.R16(G_DVSS12) U1.R17(G_DVSS11) U1.T10(G_AVSS28) U1.T11(G_DVSS10) U1.T15(G_DVSS9) U1.T19(G_DVSS8) U1.U1(G_AVSS_RF95) U1.U2(G_AVSS_RF94) U1.U3(G_AVSS_RF93) U1.U4(G_AVSS_RF92) U1.U7(G_AVSS_RF91) U1.U10(G_AVSS27) U1.U15(FSYNCI) U1.U17(G_DVSS7) U1.U18(G_DVSS6) U1.U19(G_DVSS5) U1.V1(G_AVSS_RF90) U1.V2(G_AVSS_RF89) U1.V3(G_AVSS_RF88) U1.V4(G_AVSS_RF87) U1.V5(G_AVSS_RF86) U1.V6(G_AVSS_RF85) U1.V7(G_AVSS_RF84) U1.V8(PGAP_TP) U1.V9(AD_EXTCLK) U1.V10(G_DVSS4) U1.V11(G_DVSS3) U1.V16(FSYNCO) U1.V18(SCAN_EN_TOP) U1.W2(G_AVSS_RF83) U1.W3(G_AVSS_RF82) U1.W4(G_AVSS_RF81) U1.W5(G_AVSS_RF80) U1.W6(G_AVSS_RF79) U1.W7(G_AVSS_RF78) U1.W8(PGAN_TP) U1.W9(G_AVSS26) U1.W10(G_DVSS2) U1.W15(TESTMODE) U1.W18(G_DVSS1) U4.3(GND) U8.2(GND) U10.2(GND) U11.2(GND) U12.2(GND) U14.10(GND) U15.2(GND) U16.2(GND) U19.4(VSS) U21.C15(DDR_VSSA) U21.D8(VSS_0) U21.D10(VSS_1) U21.D12(VSS_2) U21.D14(VSS_3) U21.E9(VSS_4) U21.E17(VSS_5) U21.F8(VSS_6) U21.F10(VSS_7) U21.F12(VSS_8) U21.F14(VSS_9) U21.F16(VSS_10) U21.G13(VSS_11) U21.G17(VSS_12) U21.H8(VSS_13) U21.H12(VSS_14) U21.J7(VSS_15) U21.J9(VSS_16) U21.J17(VSS_17) U21.K10(VSS_18) U21.K12(VSS_19) U21.K16(VSS_20) U21.L5(VSS_RTC) U21.L11(VSS_21) U21.L13(VSS_22) U21.L15(VSS_23) U21.L17(VSS_24) U21.M4(PLL_AVSS) U21.M6(PLL_VSS) U21.M8(VSS_25) U21.M12(VSS_26) U21.N7(VSS_27) U21.N11(VSS_28) U21.P8(VSS_29) U21.P12(VSS_30) U21.P18(DSI_AVSS) U21.R7(VSS_31) U21.R9(VSS_32) U21.R11(VSS_33) U21.T10(VSS_34) U21.T14(VSS_35) U21.T16(VSS_36) U21.T18(CSI_AVSS) U21.U9(VSS_37) U21.U13(VSS_38) U21.U15(VSS_39) U21.U17(VSS_40) U21.V8(USB_AVSS) U21.W7(SADC_AVSS) U21.W9(CODEC_AVSS) Y1.2 Y1.4 Y2.2 Y2.4 Y4.2 Y4.4
VDD12_MEM: C93.2 C94.2 C151.2 C214.1 C215.1 C223.1 C225.1 C227.1 C266.1 C267.1 L14.1 R64.2 R87.2 U21.A9(VDDMEM_0) U21.A11(VDDMEM_1) U21.B10(VDDMEM_2) U21.C9(VDDMEM_3) U21.C11(VDDMEM_4) U21.D16(VDDMEM_5) U21.E11(VDDMEM_6) U21.E13(VDDMEM_7) U21.E15(VDDMEM_8)
VIN_12V: C260.1 C261.2 D3.1 R102.1 U4.4(IN)
BOOT_SEL0: R98.2 U21.P6(BOOT_SEL0/PE25)
BOOT_SEL1: J3.3 R99.2 TP36.1(A) U21.N5(BOOT_SEL1/PE26)
BOOT_SEL2: R100.2 U21.P4(BOOT_SEL2/PE27)
BUCK_1V8: C138.2 C140.2 C146.2 C194.1 C229.1 C232.1 C234.1 C247.1 FB16.1 FB17.2 J3.4 L12.1 R75.2 R83.1 R93.2 R94.2 TP43.1(A) U8.1(EN) U16.1(EN) U21.AA7(USB_AVD18) U21.AB10(CODEC_AVDD) U21.AC3(SADC_AVDD) U21.B12(DDR_VDD1_0) U21.C13(DDR_VDD1_1) U21.H2(VDDIO_RTC) U21.K8(VDDIO_0) U21.L7(VDDIO_1) U21.N17(VDDIO18_0) U21.P20(DSI_AVD18) U21.R17(VDDIO18_1) U21.T8(VDDIO18_CIM) U21.T20(CSI_AVD18)
BUCK_3V3: C57.1 C139.2 C141.2 C143.2 C193.1 C237.1 C254.1 FB12.1 FB13.1 L11.1 R53.2 R97.2 R101.2 R103.1 U11.1(EN) U19.8(VCC) U21.M16(VDDIO33_0) U21.P16(VDDIO33_1) U21.U7(VDDIO33_CIM) U21.Y8(USB_AVD33)
BUCK_CORE: C147.2 C149.2 C153.2 C206.1 C208.1 C209.1 C216.1 C217.1 C221.1 C244.1 C249.2 C268.1 C269.1 C270.1 C271.1 FB18.2 L13.1 R61.2 U21.AB6(USB_AVD09) U21.G9(VDD_0) U21.G11(VDD_1) U21.G15(VDD_2) U21.H10(VDD_3) U21.H14(VDD_4) U21.H16(VDD_5) U21.J1(VDD_RTC) U21.J11(VDD_6) U21.J13(VDD_7) U21.J15(VDD_8) U21.K14(VDD_9) U21.L9(VDD_10) U21.M10(VDD_11) U21.M14(VDD_12) U21.N9(VDD_13) U21.N13(VDD_14) U21.N15(VDD_15) U21.N19(DSI_AVD09) U21.P10(VDD_16) U21.P14(VDD_18) U21.R13(VDD_19) U21.R15(VDD_20) U21.R19(CSI_AVD09)
CANH: C133.2 ESD15.1(ANODE) J2.10 R71.2 U12.7(CANH)
CANL: C134.1 ESD16.1(ANODE) J2.9 R72.1 U12.6(CANL)
CASCADE: R57.2 U1.P15(CASCADE)
CH_1V4: C86.2 C87.1 C88.1 FB7.1 FB8.1 FB9.1 FB11.1 L5.2 R51.1
CH_1V8: C116.1 FB1.1 FB3.1 FB5.1 FB6.1 R48.1 R83.2
CKN_PHY: U1.N18(PHY_CKN) U21.V22(RX_CLKN0)
CKP_PHY: U1.N19(PHY_CKP) U21.U21(RX_CLKP0)
D0N_PHY: U1.L19(PHY_D0N) U21.R21(RX_DATAN0)
D0P_PHY: U1.L18(PHY_D0P) U21.R23(RX_DATAP0)
D1N_PHY: U1.M19(PHY_D1N) U21.U23(RX_DATAN1)
D1P_PHY: U1.M18(PHY_D1P) U21.T22(RX_DATAP1)
D2N_PHY: U1.P18(PHY_D2N) U21.W23(RX_DATAN2)
D2P_PHY: U1.P19(PHY_D2P) U21.W21(RX_DATAP2)
D3N_PHY: U1.R18(PHY_D3N) U21.AA23(RX_DATAN3)
D3P_PHY: U1.R19(PHY_D3P) U21.Y22(RX_DATAP3)
DDR_VREF: C224.1 C225.2 R86.2 R87.1 U21.A13(VREF)
EXCLKI: C52.1 R18.1 U21.N1(EXCLK_XI) Y4.1
EXCLKO: R18.2 R90.2 U21.N3(EXCLK_XO)
EXT_12V: C272.2 F1.1 J2.1 TP14.1(A)
INT: TP28.1(A) U1.T14(INTERRUPT)
MSC2_CLK: J3.14 U21.W13(MSC2_CLK/PWM2/TCU1_IN0/PE00)
MSC2_CMD: J3.12 U21.W11(MSC2_CMD/PWM3/TCU1_IN1/PE01)
MSC2_D0: J3.9 U21.Y10(MSC2_D0/PWM4/TCU2_IN0/PE02)
MSC2_D1: J3.11 U21.V10(MSC2_D1/PWM5/TCU2_IN1/PE03)
MSC2_D2: J3.10 U21.Y12(MSC2_D2/PWM6/TCU3_IN0/PE04)
MSC2_D3: J3.13 U21.V12(MSC2_D3/PWM7/TCU3_IN1/PE05)
PB26/RST: R70.1 U14.19(RST) U21.G19(SD10/LCD_HSYNC/SLCD_WR/PB26)
PB27/INT: U14.13(INT) U21.C19(SD11/LCD_DE/SLCD_TE/PB27)
PB28/CS: U14.18(CS) U21.F20(SD12/SSI0_CE0_N/UART8_RXD/PB28)
PB29/MISO: U14.17(SO) U21.F18(SD13/SSI0_DR/UART8_TXD/PB29)
PB30/MOSI: U14.16(SI) U21.E19(SD14/SSI0_DT/UART9_RXD/PB30)
PB31/CLK: U14.14(SCK) U21.D18(SD15/SSI0_CLK/UART9_TXD/PB31)
PC01/BEEP: ESD20.1(ANODE) J2.5 U21.Y20(PWM1/TCU0_IN1/RMII0_PHY_CLK/I2S)
PC02/LED_L: ESD22.1(ANODE) J2.3 U21.AC17(PWM2/TCU1_IN0/RMII0_TXD0/I2S1_R)
PC03/LED_R: ESD21.1(ANODE) J2.4 U21.AB16(PWM3/TCU1_IN1/RMII0_TXD1/I2S1_R)
PC04/BACK_IN: ESD17.1(ANODE) J2.8 U21.Y16(PWM4/TCU2_IN0/I2S1_RX_DATA/SCC_)
PD05/CH_RST: C51.2 R31.2 U1.V19(SRSTB) U21.B8(I2C5_SDA/PCM_SYNC/PD05)
POR_BYPASS: R56.2 U1.P14(POR_BYPASS)
PPRST_N: C252.2 R93.1 U21.K6(PPRST_N)
RX1: RX1.1 U1.K1(RX1)
RX2: RX2.1 U1.M1(RX2)
RX3: RX3.1 U1.P1(RX3)
RX4: RX4.1 U1.T1(RX4)
RXCAN: U12.4(RXD) U14.2(RXCAN)
SFC0_CE_N: R103.2 U19.1(CS_N) U21.AB12(SFC0_CE_N/SSI1_DT/PE17)
SFC0_CLK: U19.6(CLK) U21.AC13(SFC0_CLK/SSI1_CLK/PE16)
SFC0_DQ0: U19.5(DI(DQ0)) U21.AA13(SFC0_DQ0/SSI1_DR/PE18)
SFC0_DQ1: U19.2(DO(DQ1)) U21.AA15(SFC0_DQ1/I2C2_SCK/PE19)
SFC0_DQ2: U19.3(WP_N(DQ2)) U21.AC15(SFC0_DQ2_WP_N/I2C2_SDA/PE20)
SFC0_DQ3_HOLD_N: U19.7(HOLD_N(DQ3)) U21.AB14(SFC0_DQ3_HOLD_N/SSI1_CE0_N/PE21)
SPI_CLK: U1.W17(SPI_CLK) U21.G1(MSC0_CLK/SFC0_CLK/SSI1_CLK/PD17)
SPI_CS: U1.U16(SPI_CS) U21.E3(MSC0_D3/SFC0_DQ3_HOLD_N/SSI1_CE)
SPI_MISO: U1.V17(SPI_MISO) U21.E1(MSC0_D0/SFC0_DQ0/SSI1_DR/PD19)
SPI_MOSI: U1.W16(SPI_MOSI) U21.G3(MSC0_CMD/SFC0_CE_N/SSI1_DT/PD18)
TX1: TX3.1 U1.A12(TX1)
TX2: TX2.1 U1.A10(TX2)
TXCAN: U12.1(TXD) U14.1(TXCAN)
UART2_RXD: J3.1 TP37.1(A) U21.B4(UART2_RXD/I2C3_SCK/PWM0/TCU0_IN)
UART2_TXD: J3.2 TP38.1(A) U21.C5(UART2_TXD/I2C3_SDA/PWM1/TCU0_IN)
UART3_RXD: ESD18.1(ANODE) J2.7 R97.1 U21.B16(UART3_RXD/I2C4_SCK/PC25)
UART3_TXD: ESD19.1(ANODE) J2.6 U21.A17(UART3_TXD/I2C4_SDA/PC26)
USB_DN: J3.6 TP40.1(A) U21.AA5(USB_DM0)
USB_DP: J3.7 TP41.1(A) U21.AC5(USB_DP0)
VSYS: C84.2 C85.2 C136.2 C142.1 C145.2 C148.1 C150.1 C256.1 C257.1 C258.1 J3.5 L2.2 R11.1 R50.2 R76.1 TP39.1(A) U8.4(VIN) U10.4(VIN) U11.4(VIN) U12.3(VCC) U15.4(VIN) U16.4(VIN)
WKUP_N: C253.2 R94.1 U21.L3(WKUP_N/PE31)
N2439824: C86.1 R51.2 R54.1 U10.5(FB)
N2440064: L5.1 U10.3(SW)
N2464554: C48.2 U1.J19(XTALI) Y1.1
N2465035: C49.2 U1.K19(XTALO) Y1.3
N2479306: R28.2 U1.G18(BGR)
N2558545: C50.2 U1.H18(DCT_GPADC)
N2669126: R50.1 U10.1(EN)
N2735799: C128.2 C129.2 FB12.2 R70.2 U14.20(VDD)
N2735943: C131.2 U14.9(OSC1) Y2.1
N2735967: C130.2 U14.8(OSC2) Y2.3
N2736087: C133.1 C134.2 C135.1
N2736303: C132.1 R71.1 R72.2
N2736527: R73.1 U12.8(STB)
N2736623: C137.2 FB13.2 U12.5(VIO)
N2737540: C141.1 R53.1 R77.1 U8.5(FB)
N2737548: R76.2 U15.1(EN)
N2737552: C140.1 R74.2 R75.1 U15.5(FB)
N2737610: L12.2 U15.3(SW)
N2737826: L11.2 U8.3(SW)
N2738138: D2.1 D3.2 F1.2
N2739230: C153.1 R61.1 R63.2 U16.5(FB)
N2739292: L13.2 U16.3(SW)
N2739406: C151.1 R64.1 R67.2 U11.5(FB)
N2739468: L14.2 U11.3(SW)
N16675046: C53.1 R90.1 Y4.3
N16679120: C205.2 C264.1 FB17.1 U21.L1(PLL_AVDD)
N16679422: R40.1 U21.AC7(USB_BIAS)
N16679836: C198.1 R101.1 U21.T12(VDDIO33_SD)
N16679980: C220.2 C265.1 FB18.1 U21.M2(PLL_VDD)
N16679984: C200.1 FB16.2 U21.A15(DDRPLL_VCCA)
N16680310: R4.1 U21.B14(ZQ)
N16680330: R89.2 U21.A5(AVDEFUSE)
N16680520: C210.1 U21.U11(VDDIO18_SD)
N16681692: C70.2 U21.AC9(CODEC_VCM)
N16703806: C263.1 L2.1 U4.5(LX)
N16704000: C256.2 R11.2 R12.1 U4.1(FB)
N16708145: C263.2 U4.6(BS)
N16719733: R102.2 U4.2(EN)

Pads without a net: U1 A1 A19 R12 R13 T12 T13 U12 U13 U14 V12 V13 V14 V15 W1 W11 W12 W13 W14 W19; U14 3 4 5 6 7 11 12 15; U21 A1 A3 A7 A19 A21 A23 AA1 AA3 AA9 AA11 AA17 AA19 AA21 AB2 AB4 AB8 AB18 AB20 AB22 AC1 AC11 AC19 AC21 AC23 B2 B6 B18 B20 B22 C1 C3 C7 C17 C21 C23 D2 D4 D6 D20 D22 E5 E7 E21 E23 F2 F4 F6 F22 G5 G21 G23 H4 H6 H18 H20 H22 J3 J5 J19 J21 J23 K2 K4 K18 K20 K22 L19 L21 L23 M18 M20 M22 N21 N23 P2 P22 R1 R3 R5 T2 T4 T6 U1 U3 U5 U19 V2 V4 V6 V14 V16 V18 V20 W1 W3 W5 W15 W17 W19 Y2 Y4 Y6 Y14 Y18

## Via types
v1: diameter 0.3, hole 0.15, 03-POWER to BOTTOM, 423 vias
v2: diameter 0.4, hole 0.2, TOP to BOTTOM, 460 vias
v3: diameter 0.23, hole 0.15, 03-POWER to BOTTOM, 3 vias
v4: diameter 0.23, hole 0.15, TOP to 02-GND1, 155 vias
v5: diameter 0.3, hole 0.15, TOP to 02-GND1, 504 vias

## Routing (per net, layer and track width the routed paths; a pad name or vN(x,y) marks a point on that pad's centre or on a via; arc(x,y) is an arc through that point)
AVDD14_RX: length 13.8
  TOP w0.22: U1.R6 v2(9.75,22.97) U1.U6 ; U1.N6 v2(10.38,23.59) ; U1.J6 v2(11.65,24.86) ; U1.L6 v2(11.03,24.24)
  BOTTOM w0.4: C11.2 11.91,25.13 C12.2 ; C11.2 C14.2 ; C11.2 v2(11.65,24.86) ; C15.2 v2(10.38,23.59) ; C15.2 C14.2 ; C15.2 C13.2 ; C14.2 v2(11.03,24.24) ; C13.2 9.31,22.53 8.74,22.53 8.09,23.18 8.09,24.35 C97.2 C96.2 C95.2 7.15,26.01 FB8.2 ; C13.2 v2(9.75,22.97)
AVDD14_SX: length 9.5
  TOP w0.3: U1.E18 U1.E17 v2(16.45,23.34) ; U1.K12 v2(13.77,23.24) ; U1.G14 v2(15.45,23.06)
  BOTTOM w0.35: 15.86,23.13 v2(15.45,23.06) C36.2 v2(13.77,23.24) ; 15.86,23.13 15.86,23.14 C35.2 ; 15.86,23.13 16.05,23.34
  BOTTOM w0.4: FB9.2 16.69,26.16 C98.2 16.69,25.62 C99.2 17.1,25.2 C100.2 17.42,24.23 C37.2 16.95,24.23 C38.2 16.48,23.37 v2(16.45,23.34) 16.05,23.34
AVDD14_TX: length 12.9
  TOP w0.22: U1.E13 v2(15.17,24.66) ; U1.E7 v2(13.25,26.59) U1.E5 ; v2(14.52,25.31) U1.E11 ; v2(13.9,25.94) U1.E9
  BOTTOM w0.4: 13.58,26.27 v2(13.9,25.94) C2.2 ; 13.58,26.27 C2.2 ; 13.58,26.27 C1.2 ; C2.2 C4.2 ; C4.2 v2(15.17,24.66) C5.2 C4.2 ; C4.2 v2(14.52,25.31) ; FB7.2 14.83,29.48 C90.2 14.16,28.79 C91.2 C92.2 13.5,28.13 12.77,27.4 12.77,27.08 C1.2 ; v2(13.25,26.59) C1.2
AVDD18_RX: length 13.7
  TOP w0.22: U1.N5 v2(10.6,24.67) ; U1.U5 v2(9.32,23.39) ; 9.71,23.67 v2(9.97,24.04)
  TOP w0.3: U1.J5 v2(11.25,25.29) U1.L5
  02-GND1 w0.3: 11.62,27.81 v4(11.94,27.81) ; 11.62,27.81 11.16,28.26 v2(11.16,28.26) ; 11.62,27.81 v4(11.62,27.49)
  BOTTOM w0.3: 10.55,26.91 10.55,27.27 10.49,27.34 10.95,27.81 C22.2 11.09,27.94 11.09,28.19 v2(11.16,28.26)
  BOTTOM w0.4: C20.2 9.02,23.09 v2(9.32,23.39) 9.64,23.7 C19.2 9.64,23.71 v2(9.97,24.04) 9.97,24.04 C18.2 v2(10.6,24.67) C17.2 v2(11.25,25.29) C16.2 11.4,25.83 11.4,26.15 10.64,26.91 10.55,26.91 C74.2 C73.2 9.57,27.24 C72.2 8.9,27.92 FB3.2
AVDD18_TX: length 13
  TOP w0.22: U1.F5 v2(12.84,26.15) U1.F7 ; v2(14.15,24.86) U1.F11 ; v2(13.47,25.51) U1.F9 ; U1.F13 v2(14.77,24.24)
  BOTTOM w0.4: C7.2 C6.2 12.52,26.49 12.19,26.82 12.19,27.58 C68.2 12.06,28.45 11.53,28.99 C67.2 C66.2 11.52,30.15 FB1.2 ; C7.2 v2(13.47,25.51) ; C7.2 v2(12.84,26.15) ; C7.2 C8.2 ; C9.2 v2(14.15,24.86) C8.2 ; C9.2 C10.2 v2(14.77,24.24) ; C9.2 C8.2
AVDD18_XO: length 5.9
  02-GND1 w0.2: v4(15.12,21.44) 14.55,21.44 14.43,21.56 v2(13.9,21.56)
  BOTTOM w0.28: C39.2 14.7,21.26 14.37,21.6 13.93,21.6 v2(13.9,21.56)
  BOTTOM w0.35: C39.2 15.45,21.26 15.59,21.13 C77.2 C76.2 C75.2 15.59,18.5 R48.2
DVDD14: length 23.5
  TOP w0.22: U1.L9 v2(12.24,24.23) ; U1.R9 v2(10.77,22.63) ; U1.U9 v2(10.08,21.93) ; U1.N9 v2(11.51,23.33)
  TOP w0.3: v2(13.43,21.23) 13.22,21.44 U1.N14 U1.N13 U1.N12
  TOP w0.4: v2(14.84,26.86) 14.84,26.86 v2(14.56,26.58)
  02-GND1 w0.2: v4(15.44,21.12) 15.44,20.71 16.11,20.03 16.45,20.03 16.91,19.58 v2(17.3,19.58)
  03-POWER w0.25: 10.65,21.92 10.65,21.93 v2(10.08,21.93) ; 11.54,23.3 11.93,23.3 ; 11.57,22.88 11.57,23.27 v2(11.51,23.33) ; 12.35,23.69 12.32,23.69 12.32,24.15 v2(12.24,24.23) ; 10.84,22.56 11.21,22.56 ; 15.98,23.42 15.98,23.42 15.98,23.15 16.25,22.88 16.25,22.23 15.9,21.89 15.9,20.24 16.56,19.58 v2(17.3,19.58) ; v2(10.77,22.63) 10.77,22.2 10.78,22.19
  03-POWER w0.35: v2(10.08,21.93) 10.45,21.56 10.47,21.56 ; v2(10.77,22.63) 11.09,22.31 11.12,22.31 ; 12.71,24.02 12.5,24.23 v2(12.24,24.23) 12.24,24.23 12.65,23.82 ; v2(11.51,23.33) 11.51,23.33 11.87,22.96
  BOTTOM w0.2: C27.2 v2(17.3,19.58)
  BOTTOM w0.3: C26.2 10.08,21.54 10.07,21.72 v2(10.08,21.93) ; C23.2 v2(10.77,22.63) ; C42.2 v2(13.43,21.23) ; C25.2 v2(12.24,24.23) ; C24.2 v2(11.51,23.33)
  BOTTOM w0.4: v2(14.56,26.58) 14.84,26.86 v2(14.84,26.86) C106.2 C105.2 16.41,28.43 C104.2 16.41,29.18 FB11.2
DVDD18: length 15.9
  TOP w0.22: U1.M9 v2(11.84,23.72) ; U1.K9 v2(12.96,24.55) ; U1.L17 v2(14.2,21.12)
  TOP w0.3: U1.T9 v2(10.34,22.37) ; U1.P9 v2(11.14,22.98) ; U1.H15 v2(14.89,22.49) ; U1.G17 v2(15.8,22.64)
  TOP w0.4: v2(12.29,29.52) v2(12.29,29.96)
  02-GND1 w0.25: v4(12.57,21.44) v2(11.84,23.72)
  03-POWER w0.25: 11.09,23.5 11.09,23.04 v2(11.14,22.98) ; 11.81,23.75 11.53,23.75 ; 10,22.35 10.32,22.35 v2(10.34,22.37) 10.34,22.71 ; v2(11.84,23.72) 11.84,24.03 ; 10.68,23.05 10.95,23.05 11.02,22.98 11.11,22.98
  03-POWER w0.35: 10.77,23.31 11.11,22.98 v2(11.14,22.98) ; 11.52,24.06 11.52,24.04 v2(11.84,23.72) ; 10.07,22.61 10.32,22.37 v2(10.34,22.37)
  BOTTOM w0.25: v2(10.34,22.37) 10.39,22.35 10.48,22.13 10.52,21.95 C33.2
  BOTTOM w0.3: C29.2 v2(11.14,22.98) ; C30.2 v2(11.84,23.72) ; C32.2 v2(12.96,24.55)
  BOTTOM w0.35: C31.2 14.87,22.47 v2(14.89,22.49) ; C28.2 v2(15.8,22.64)
  BOTTOM w0.4: FB5.2 11.65,31.97 12.3,31.32 C83.2 12.29,31.22 C82.2 12.29,30.3 v2(12.29,29.96) v2(12.29,29.52) C81.2
DVDD_GPIO: length 9.3
  TOP w0.22: v2(12.97,19.74) 13,19.74 U1.T17 U1.T18
  02-GND1 w0.3: v4(10.98,21.12) v2(10.49,19.7)
  BOTTOM w0.2: C46.2 13.58,18.97 13.21,18.6 R31.1
  BOTTOM w0.3: v2(10.49,19.7) 10.53,19.74 C45.2
  BOTTOM w0.35: C45.2 v2(12.97,19.74) 13.18,19.54 C46.2 C44.2 14.67,19.11 FB6.2
GND: length 60.8
  TOP w0.1: 16.85,21.12 16.71,21.12 U1.H19 ; v2(16.55,21.06) 16.57,21.09 16.95,21.09 17.16,21.1 v2(17.21,21.05) ; U1.L12 v2(12.89,22.72) ; v5(4.51,30.63) 4.52,30.64 4.52,30.79 4.64,30.91 v5(4.7,30.91) ; C48.1 18,21.84 ; C49.1 18.23,19.77 18.33,19.67
  TOP w0.15: U1.G19 v4(16.9,21.59)
  TOP w0.2: 12.57,18.26 12.57,18.03 v2(12.44,17.9) ; v2(13.66,18.25) 13.66,18.45 U1.U19
  TOP w0.25: C49.1 17.84,20.24 17.64,20.05 17.08,20.05 ; v2(17.21,21.05) v2(17.49,21.34)
  TOP w0.3: 17.09,20.06 v2(17.05,20.02)
  TOP w0.4: 19.1,19.67 20.73,19.67 v2(20.74,19.66) v2(20.74,20.7) v2(20.74,21.65) 20.72,21.67 Y1.4 v2(20,22.45) ; 19.1,19.67 v2(19.08,19.67) 17.98,19.67 ; 19.1,19.67 19.1,19.68 Y1.2 ; v5(21.28,22.1) Y2.2 v2(22.12,22.84) ; 18,21.84 18.23,22.07 18.62,22.47 v2(19.06,22.47) ; C57.2 v2(7.82,5.95) ; C254.2 10.88,5.95 v2(11.13,6.21) ; Y2.4 v2(24.29,21.2) ; v2(15.65,5.08) 15.87,5.3 C205.1
  BOTTOM w0.1: v2(2.85,23.59) 2.79,23.65 1.9,23.65 ; C2.1 14.59,25.96 14.67,25.96 ; v2(3.6,23.61) 3.55,23.67 3.55,23.79 3.39,23.95 2.82,23.95 ; C26.1 10.62,21.02 10.62,21.06 ; 2.82,23.95 J2.11 1.9,23.65 ; 2.82,23.95 v2(3.77,24.9) ; 19.64,29.5 19.38,29.5 19.11,29.76 ; 1.9,23.65 1.9,23.03 2,22.93 2.59,22.93 2.59,22.74 2.73,22.59 2.94,22.59 3.09,22.74 3.09,22.93 3.78,22.93 v2(3.88,22.84) ; 8.28,31.31 8.42,31.17 8.42,30.31 8,29.89 8,29.87 ; v1(14.51,27.48) 14.16,27.48 C92.1 ; 11.35,27.58 v1(11.35,27.59)
  BOTTOM w0.15: v1(11.35,27.59) 11.43,27.51 C68.1 ; v1(10.43,28.32) 10.59,28.16 C22.1 ; v2(19.39,30.74) 19.24,30.58 C93.1 ; C3.1 13.98,26.62 14.25,26.35
  BOTTOM w0.25: 15.54,9.87 v2(15.54,9.87) 15.54,9.87 ; 15.54,9.87 U21.N11 ; U21.P18 U21.T18 v2(14.68,13.31) ; U21.T10 14.68,9.87 v2(14.68,9.87) ; v2(14.68,11.59) 14.68,11.59 U21.U15 ; U21.D10 v2(19.84,9.01) U21.D8 ; U21.J7 18.12,8.15 v2(18.12,8.15) ; v2(17.26,9.87) 17.26,9.87 U21.L11 ; U21.J9 17.26,9.01 v2(17.26,9.01) ; v2(17.05,20.02) 16.84,20.22 C76.1 ; U21.L5 16.4,7.29 v2(16.4,7.29) U21.M4 ; U21.T14 14.25,11.16 v2(14.25,11.16) ; U21.D14 20.27,11.16 v2(20.27,11.16) ; U21.F12 v2(18.98,9.87) ; v2(13.82,8.15) 13.82,8.15 U21.V8 ; v2(16.83,10.3) 16.83,10.3 U21.L13 ; v2(18.98,12.45) 18.98,12.45 U21.E17 ; U21.E9 18.98,9.01 v2(18.98,9.01) ; U21.J17 v2(18.12,12.45) ; v2(9.64,5.33) 9.08,5.33 C136.1 ; U21.U17 v2(14.25,12.88) ; U21.R7 v2(15.11,8.58) ; v2(18.55,10.3) 18.55,10.3 U21.G13 ; v2(17.26,12.45) 17.26,12.45 U21.K16 ; U21.L17 v2(16.83,12.02)
  BOTTOM w0.254: U21.H8 v2(18.12,8.15) ; U21.R11 v2(14.68,9.87) ; U21.G17 v2(18.12,12.45) ; U21.L15 v2(16.83,12.02) ; U21.U9 v2(14.68,9.01) ; U21.F10 v2(18.98,9.87) ; U21.H12 v2(18.55,10.3) ; U21.W7 v2(13.82,8.15) ; U21.C15 v2(20.27,11.16) ; U21.R9 v2(15.11,8.58) ; U21.K12 v2(17.26,9.87) ; U21.M6 v2(16.4,7.29) ; U21.T16 v2(14.68,11.59) ; U21.F8 v2(18.98,9.01) ; U21.F16 v2(18.98,12.45) ; U21.U13 v2(14.25,11.16) ; U21.D12 v2(20.2,10.3) ; U21.K10 v2(17.26,9.01) ; U21.M12 v2(16.83,10.3) ; U21.P12 v2(15.54,9.87) ; U21.P8 v2(15.54,8.15) ; U21.M8 v2(16.4,8.15)
  BOTTOM w0.3: ESD18.2 v2(6.62,14.74) ; ESD19.2 v2(6.67,15.99) ; ESD17.2 v2(5.85,13.39) ; ESD16.2 v2(5.85,11.64) ; ESD15.2 5.85,9.91 v2(5.72,10.04)
  BOTTOM w0.35: C7.1 v2(13.1,25.14) C8.1
  BOTTOM w0.4: v2(13.79,4.84) 13.8,4.83 Y4.4 v2(13.09,4.03) ; C53.2 15.14,2.05 v2(15.13,2.04) v2(14.68,2.04) 14.7,2.07 Y4.2 ; C52.2 v2(15.65,5.08)
  vias: v1(3.13,34.62) v1(3.32,39.71) v1(3.4,39.13) v1(3.43,38.53) v1(3.42,37.98) v1(3.39,37.34) v1(3.4,36.58) v1(3.48,39.98) v1(3.54,34.09) v1(3.61,39.56) v1(3.73,40.19) v1(3.85,39.89) v1(3.88,37.75) v1(3.86,37.11) v1(3.87,34.66) v1(3.97,40.37) v1(4.08,33.95) v1(4.24,40.05) v1(4.24,37.45) v1(4.23,36.56) v1(4.24,33.34) v1(4.41,40.36) v1(4.37,38.14) v1(4.58,39.87) v1(4.72,36.56) v1(4.71,34.12) v1(4.72,33.51) v1(4.74,32.84) v1(4.79,40.73) v1(4.77,40.16) v1(4.78,38.84) v1(4.76,37.38) v1(5.04,38.33) v1(4.98,37.8) v1(4.98,36.97) v1(5.45,38.75) v1(5.61,35.13) v1(5.76,37.67) v1(5.77,36.9) v1(5.76,36.2) v1(5.94,33.49) v1(6.11,32.66) v1(6.24,34.57) v1(6.34,38.43) v1(6.59,40.9) v1(6.62,33.92) v1(6.85,40.62) v1(6.81,33.27) v1(6.88,39.89) v1(6.86,38.94) v1(6.87,38.39) v1(7.03,40.28) v1(7.2,34.6) v1(7.44,40.3) v1(7.36,39.93) v1(7.42,33.92) v1(7.8,27.88) v1(7.77,27.04) v1(7.79,26.65) v1(7.84,26.18) v1(7.9,39.92) v1(7.88,27.4) v1(8.03,40.32) v1(8.24,34.6) v1(8.16,25.89) v1(8.5,40.89) v1(8.51,40.38) v1(8.51,39.97) v1(8.48,38.59) v1(8.62,38.13) v1(8.73,39.08) v1(8.71,37.61) v1(8.71,36.99) v1(8.88,40.92) v1(8.9,40.28) v1(8.95,38.54) v1(9.03,36.56) v1(9.14,39.94) v1(9.07,38.1) v1(9.16,37.69) v1(9.46,36.92) v1(9.55,38.05) v1(9.6,30.7) v1(9.67,37.41) v1(9.69,29.82) v1(9.68,28.01) v1(9.71,25.93) v1(9.78,28.62) v1(9.91,31.01) v1(9.85,29.23) v1(9.98,36.56) v1(10.19,40.48) v1(10.16,39.97) v1(10.15,38.1) v1(10.18,37.24) v1(10.21,29.01) v1(10.27,29.58) v1(10.63,30.14) v1(10.63,29.23) v1(10.83,29.68) v1(10.91,34.54) v1(10.89,32.89) v1(11,30.35) v1(11.01,28.78) v1(11.22,35.41) v1(11.33,37.62) v1(11.29,36.67) v1(11.3,33.73) v1(11.5,27.97) v1(11.84,38.44) v1(11.97,34.46) v1(12,32.9) v1(12.19,40.91) v1(12.45,39.19) v1(12.39,38.64) v1(12.55,40.51) v1(12.49,39.92) v1(12.53,33.74) v1(12.6,40.87) v1(12.63,32.34) v1(12.9,40.18) v1(12.88,30.89) v1(13.11,39.88) v1(13.13,34.46) v1(13.14,30.72) v1(13.18,32.92) v1(13.34,40.3) v1(13.33,30.42) v1(13.26,29.75) v1(13.3,28.68) v1(13.47,29.23) v1(13.65,39.89) v1(13.63,32.36) v1(13.57,30.72) v1(13.61,30.24) v1(13.69,29.82) v1(13.81,33.73) v1(13.91,40.46) v1(13.97,38.53) v1(13.95,16.45) v1(14.13,39.93) v1(14.1,29.51) v1(14.22,38.94) v1(14.19,38.06) v1(14.24,37.01) v1(14.16,27.56) v1(14.34,40.9) v1(14.3,34.45) v1(14.3,17.04) v1(14.36,40.39) v1(14.42,32.86) v1(14.47,38.58) v1(14.48,28.11) v1(14.62,38.08) v1(14.58,37.55) v1(14.6,36.56) v1(14.7,39.95) v1(14.69,37.09) v1(14.66,28.59) v1(14.8,19.78) v1(14.87,27.77) v1(15.04,38.02) v1(15.05,37.35) v1(15.02,28.86) v1(14.97,28.26) v1(15.09,36.86) v1(15.07,36.34) v1(15.06,20.15) v1(15.06,19.42) v1(15.23,28.5) v1(15.52,37.56) v1(15.48,28.8) v1(15.6,40.29) v1(15.55,36.56) v1(15.64,28.41) v1(15.77,38.88) v1(15.78,38.03) v1(15.86,38.51) v1(15.92,37.04) v1(15.96,27) v1(16.24,34.87) v1(16.22,30.88) v1(16.18,25.91) v1(16.25,26.72) v1(16.39,38.78) v1(16.43,27.69) v1(16.39,27.14) v1(16.39,24.95) v1(16.39,24.31) v1(16.37,21.39) v1(16.47,20.24) v1(16.47,18.98) v1(16.64,21.81) v1(16.72,36.33) v1(16.68,35.39) v1(16.66,22.68) v1(16.79,37.75) v1(16.82,34.77) v1(16.8,24.7) v1(16.99,27.96) v1(17.02,22.16) v1(17.11,23.56) v1(17.21,28.33) v1(17.17,22.98) v1(17.21,21.69) v1(17.34,38.4) v1(17.5,34.64) v1(17.72,40.89) v1(17.94,39.91) v1(17.91,39.06) v1(17.87,38.55) v1(18.08,40.39) v1(18.41,34.66) v1(18.47,39.95) v1(18.71,40.35) v1(19.03,39.93) v1(19.27,40.34) v1(19.47,40.87) v1(19.5,38.5) v1(19.64,39.92) v1(19.72,38.94) v1(19.71,37.85) v1(19.92,40.34) v1(19.94,38.53) v1(19.87,37.25) v1(19.98,40.86) v1(20.15,39.94) v1(20.12,38.07) v1(20.07,36.56) v1(20.36,37.61) v1(20.55,36.92) v1(20.55,40.3) v1(20.55,36.27) v1(20.71,38.12) v1(20.81,40.03) v1(20.84,31.76) v1(20.93,37.52) v1(20.91,32.09) v1(21.02,36.56) v1(21.04,31.43) v1(21.11,32.37) v1(21.18,39.97) v1(21.18,31.89) v1(21.25,40.56) v1(21.33,37.97) v1(21.29,37.1) v1(21.32,32.67) v1(21.41,38.61) v1(21.53,32.42) v1(21.62,32.83) v1(21.57,32) v1(21.61,31.66) v1(21.56,28.61) v1(21.73,38.41) v1(21.82,32.31) v1(21.92,38.84) v1(21.92,31.95) v1(22.14,32.2) v1(22.15,37.55) v1(22.17,36.88) v1(22.15,36.26) v1(22.34,33.73) v1(22.82,30.3) v1(22.81,29.45) v1(22.9,14.77) v1(22.9,14.43) v1(22.89,13.35) v1(22.97,14.01) v1(23.26,30.48) v1(23.3,14.45) v1(23.3,13.55) v1(23.3,12.35) v1(23.3,11.45) v1(23.3,10.55) v1(23.3,9.65) v1(23.3,7.05) v1(23.3,6.15) v1(23.39,29.87) v1(23.58,14.77) v1(23.58,13.99) v1(23.86,30.75) v1(24.09,31.92) v1(24.07,31.52) v1(24.43,32.12) v1(24.6,17.49) v2(0.43,40.78) v2(0.42,19.7) v2(0.44,18.69) v2(0.43,17.05) v2(0.44,15.42) v2(0.45,9.03) v2(0.45,8.4) v2(0.44,7.6) v2(0.43,6.75) v2(0.41,5.71) v2(0.43,4.68) v2(0.46,41.28) v2(0.46,40.28) v2(0.46,39.28) v2(0.46,38.28) v2(0.46,37.28) v2(0.46,36.28) v2(0.46,35.28) v2(0.46,34.28) v2(0.46,33.28) v2(0.46,32.28) v2(0.46,31.28) v2(0.46,30.28) v2(0.45,29.2) v2(0.46,28.69) v2(0.45,28.1) v2(0.48,24) v2(0.52,12.57) v2(0.49,11.65) v2(0.53,10.81) v2(0.48,9.92) v2(0.47,3.69) v2(1.68,43.1) v2(1.67,33.14) v2(1.69,32.21) v2(1.71,31.21) v2(2.18,22.55) v2(2.2,21.76) v2(2.19,21) v2(2.2,20.26) v2(2.82,24.45) v2(2.84,22.84) v2(2.86,22.13) v2(2.94,21.38) v2(2.87,20.65) v2(3.19,14.16) v2(3.17,13.37) v2(3.23,9.41) v2(3.25,10.86) v2(3.26,0.42) v2(3.51,8.07) v2(4.04,24.21) v2(4.25,0.42) v2(4.6,27.78) v2(4.73,6.52) v2(4.83,9.32) v2(5.27,7.06) v2(5.57,19.74) v2(5.86,7.65) v2(5.94,0.43) v2(6.32,2.42) v2(6.42,19.78) v2(6.43,0.92) v2(6.51,12.13) v2(6.73,17.2) v2(6.83,2.42) v2(6.94,19.56) v2(6.9,0.43) v2(7,23.24) v2(6.99,22.71) v2(7.02,11.62) v2(7.07,11.1) v2(7.24,19.07) v2(7.37,16.8) v2(7.41,2.42) v2(7.39,0.92) v2(7.66,5.09) v2(7.67,4.03) v2(7.82,0.43) v2(8.22,2.42) v2(8.31,0.91) v2(8.72,21.76) v2(8.86,0.42) v2(8.96,23.79) v2(9.22,7.47) v2(9.35,0.9) v2(9.36,21.09) v2(9.59,24.42) v2(9.7,17.79) v2(9.92,30.37) v2(9.92,20.5) v2(9.86,0.43) v2(10.24,25.06) v2(10.59,16.83) v2(10.68,25.72) v2(11.81,26.46) v2(11.83,0.43) v2(12,17.65) v2(11.99,17.11) v2(12.16,25.7) v2(12.4,0.42) v2(12.49,16.84) v2(12.53,6.86) v2(12.73,2.36) v2(12.9,5.08) v2(13.1,4.58) v2(13.14,3.43) v2(13.19,22.42) v2(13.42,0.4) v2(13.64,26.96) v2(13.71,24.24) v2(13.85,20.52) v2(14.01,27.23) v2(14.25,23.77) v2(14.16,2.03) v2(14.68,14.17) v2(14.67,5.04) v2(14.78,21.87) v2(14.78,0.41) v2(15.06,25.89) v2(15.64,25.19) v2(15.87,23.88) v2(16.57,0.4) v2(16.82,18.6) v2(16.82,18.17) v2(16.81,17.66) v2(16.81,17.14) v2(17.04,28.77) v2(17.16,3.46) v2(17.19,2.84) v2(17.18,2.06) v2(17.8,3.47) v2(17.78,2.62) v2(18.32,3.18) v2(18.43,24.38) v2(18.62,25.66) v2(18.72,26.46) v2(18.7,1.43) v2(18.97,8.15) v2(19.09,18.61) v2(19.06,0.4) v2(19.27,2.04) v2(19.44,26.02) v2(19.5,27.15) v2(19.71,2.45) v2(19.84,8.15) v2(19.87,23.74) v2(19.92,0.89) v2(19.9,0.42) v2(20,4.67) v2(20.06,18.79) v2(20.29,1.51) v2(20.55,0.98) v2(20.53,0.43) v2(21.06,1.87) v2(21.14,1.11) v2(21.19,2.38) v2(21.28,4) v2(21.53,6) v2(21.51,4.57) v2(21.59,25.95) v2(21.63,0.41) v2(22.1,25.29) v2(22.32,29.87) v2(22.34,29.26) v2(22.48,5.12) v2(22.61,24.82) v2(22.62,0.41) v2(22.77,4.1) v2(22.87,29.89) v2(22.87,25.24) v2(23.33,24.81) v2(23.43,30.89) v2(23.43,29.36) v2(23.68,30.3) v2(23.69,25.39) v2(23.74,0.41) v2(23.79,24.38) v2(23.85,12.34) v2(23.84,10.61) v2(23.84,9.76) v2(23.85,9.22) v2(23.85,8.35) v2(23.83,7.37) v2(23.81,6.62) v2(23.84,6.05) v2(23.95,24.89) v2(23.93,23.77) v2(23.85,11.44) v2(23.99,43.07) v2(23.95,29.76) v2(24.03,22.9) v2(23.99,19.52) v2(24.05,20.71) v2(24.13,3.76) v2(24.2,29.17) v2(24.18,21.85) v2(24.28,31.12) v2(24.32,24.47) v2(24.43,5.32) v2(24.55,30.61) v2(24.53,28.88) v2(24.5,23.35) v2(24.55,0.8) v2(24.57,42.56) v2(24.59,41.61) v2(24.59,40.61) v2(24.59,39.61) v2(24.59,38.61) v2(24.59,37.61) v2(24.59,36.61) v2(24.59,35.61) v2(24.59,34.61) v2(24.59,33.61) v2(24.58,32.59) v2(24.58,31.54) v2(24.56,29.85) v2(24.59,28.33) v2(24.59,26.69) v2(24.59,25.82) v2(24.59,24.94) v2(24.58,22.37) v2(24.59,20.15) v2(24.59,19.49) v2(24.59,12.43) v2(24.59,11.49) v2(24.58,10.58) v2(24.59,9.52) v2(24.59,8.5) v2(24.59,7.4) v2(24.59,6.12) v2(24.55,4.9) v2(24.58,4.45) v2(24.58,3.79) v2(24.59,3.18) v2(24.59,1.26) v4(7.48,23.99) v4(7.48,23.35) v4(7.8,24.31) v4(7.8,23.67) v4(7.8,23.03) v4(8.12,23.99) v4(8.12,23.35) v4(8.12,22.72) v4(8.44,24.94) v4(8.44,23.67) v4(8.44,23.03) v4(8.44,22.4) v4(8.75,24.62) v4(8.75,23.35) v4(8.75,22.72) v4(8.75,22.08) v4(9.07,25.58) v4(9.07,24.31) v4(9.07,22.4) v4(9.07,21.76) v4(9.39,25.26) v4(9.39,23.99) v4(9.39,22.08) v4(9.39,21.44) v4(9.71,26.22) v4(9.71,24.94) v4(9.71,22.4) v4(9.71,21.12) v4(10.03,25.9) v4(10.03,24.62) v4(10.03,21.44) v4(10.03,20.81) v4(10.35,26.85) v4(10.35,25.58) v4(10.35,23.03) v4(10.35,21.12) v4(10.66,27.17) v4(10.66,26.53) v4(10.66,25.26) v4(10.66,21.44) v4(10.98,27.49) v4(10.98,26.85) v4(10.98,26.22) v4(10.98,23.67) v4(10.98,21.76) v4(11.3,27.17) v4(11.3,26.53) v4(11.3,25.9) v4(11.3,22.08) v4(11.3,21.44) v4(11.62,26.85) v4(11.62,24.31) v4(11.62,22.4) v4(11.62,21.76) v4(11.62,19.22) v4(11.94,28.44) v4(11.94,27.17) v4(11.94,22.08) v4(12.25,28.76) v4(12.25,28.13) v4(12.25,27.49) v4(12.25,26.22) v4(12.25,24.94) v4(12.25,19.85) v4(12.57,29.08) v4(12.57,28.44) v4(12.57,27.81) v4(12.57,23.35) v4(12.57,20.17) v4(12.89,28.76) v4(12.89,28.13) v4(12.89,25.58) v4(12.89,23.67) v4(12.89,20.49) v4(12.89,19.22) v4(12.89,18.58) v4(13.21,28.44) v4(13.21,27.17) v4(13.21,23.35) v4(13.21,22.08) v4(13.21,20.17) v4(13.21,18.9) v4(13.53,28.76) v4(13.53,28.13) v4(13.53,27.49) v4(13.53,24.94) v4(13.53,22.4) v4(13.53,20.49) v4(13.53,19.85) v4(13.85,28.44) v4(13.85,27.81) v4(13.85,26.53) v4(13.85,22.08) v4(13.85,20.17) v4(14.16,28.13) v4(14.16,26.85) v4(14.16,24.31) v4(14.16,20.49) v4(14.48,27.81) v4(14.48,27.17) v4(14.48,25.9) v4(14.48,23.35) v4(14.48,20.81) v4(14.8,27.49) v4(14.8,26.22) v4(14.8,23.67) v4(14.8,23.03) v4(15.12,26.53) v4(15.12,25.26) v4(15.12,22.08) v4(15.44,26.85) v4(15.44,25.58) v4(15.44,23.67) v4(15.44,22.4) v4(15.44,21.76) v4(15.75,25.9) v4(15.75,24.62) v4(15.75,22.08) v4(15.75,21.44) v4(16.07,26.22) v4(16.07,24.94) v4(16.39,25.26) v4(16.39,24.62) v4(16.39,22.72) v4(16.71,25.58) v4(16.71,24.94) v4(16.71,24.31) v4(16.71,23.67) v4(16.71,22.4) v4(17.03,25.26) v4(17.03,24.62) v4(17.03,23.99) v4(17.03,23.35) v4(17.35,24.94) v4(17.35,24.31) v4(17.35,23.67) v4(17.35,23.03) v4(17.66,24.62) v4(17.66,23.99) v4(17.66,23.35) v4(17.66,22.72) v4(17.98,24.31) v4(17.98,23.67) v4(17.98,23.03) v4(18.3,23.99) v4(18.3,23.35) v5(1.06,14.72) v5(1.07,13.34) v5(1.23,14.37) v5(1.54,13.8) v5(1.53,13.32) v5(1.81,6.37) v5(2.34,13.44) v5(2.39,43.12) v5(2.39,42.67) v5(2.39,42.17) v5(2.37,41.69) v5(2.37,41.25) v5(2.39,40.8) v5(2.39,40.3) v5(2.39,39.82) v5(2.39,39.35) v5(2.39,38.9) v5(2.39,38.4) v5(2.39,37.92) v5(2.39,37.39) v5(2.39,36.94) v5(2.39,36.44) v5(2.39,35.96) v5(2.39,35.51) v5(2.39,35.06) v5(2.39,34.56) v5(2.39,34.09) v5(2.39,33.61) v5(2.39,33.16) v5(2.39,32.66) v5(2.39,32.19) v5(2.41,31.66) v5(2.38,14.12) v5(2.54,31.28) v5(2.74,42.9) v5(2.74,42.45) v5(2.74,41.95) v5(2.74,41.47) v5(2.74,41) v5(2.74,40.55) v5(2.74,40.05) v5(2.74,39.57) v5(2.74,39.1) v5(2.74,38.65) v5(2.74,38.15) v5(2.74,37.67) v5(2.74,37.16) v5(2.74,36.71) v5(2.74,36.21) v5(2.74,35.74) v5(2.74,35.26) v5(2.74,34.81) v5(2.74,34.31) v5(2.74,33.84) v5(2.74,33.36) v5(2.74,32.91) v5(2.74,32.41) v5(2.74,31.91) v5(2.85,31.59) v5(2.79,7.31) v5(3.02,31.24) v5(3.14,7.3) v5(3.27,31.59) v5(3.34,6.34) v5(3.45,2.39) v5(3.52,31.24) v5(3.68,13.22) v5(3.77,31.59) v5(3.77,3.34) v5(3.83,1.85) v5(3.94,13.69) v5(3.97,31.24) v5(4.22,31.59) v5(4.16,3.35) v5(4.17,2.36) v5(4.32,31.26) v5(4.3,30.92) v5(4.4,14.06) v5(4.4,7.14) v5(4.61,13.62) v5(4.58,8.73) v5(4.67,31.59) v5(4.67,31.26) v5(4.73,30.16) v5(4.85,30.51) v5(5.13,30.2) v5(5.08,29.82) v5(5.1,13.28) v5(5.27,8.05) v5(5.37,29.54) v5(5.41,13.97) v5(5.38,2.88) v5(5.47,29.88) v5(5.63,29.26) v5(5.72,31.59) v5(5.72,31.01) v5(5.77,29.59) v5(5.83,29.02) v5(5.84,26.64) v5(5.84,12.43) v5(5.8,10.52) v5(5.85,28.68) v5(5.85,28.18) v5(5.85,27.68) v5(5.85,27.18) v5(5.92,26.14) v5(5.97,31.31) v5(5.98,30.75) v5(6.03,2.23) v5(6.06,29.29) v5(6.1,25.64) v5(6.13,14.05) v5(6.05,3.49) v5(6.17,31.59) v5(6.19,31.02) v5(6.15,28.93) v5(6.15,28.43) v5(6.15,27.93) v5(6.15,27.43) v5(6.15,26.92) v5(6.21,26.42) v5(6.27,30.44) v5(6.32,25.98) v5(6.37,31.31) v5(6.38,30.75) v5(6.37,25.29) v5(6.41,13.42) v5(6.41,12.76) v5(6.38,11.75) v5(6.51,25.63) v5(6.65,31.59) v5(6.61,30.13) v5(6.64,4.41) v5(6.65,31.08) v5(6.7,30.73) v5(6.67,24.94) v5(6.82,30.41) v5(6.77,25.3) v5(6.82,13.94) v5(6.85,29.78) v5(6.88,3.13) v5(7.03,30.1) v5(7.02,25.02) v5(6.96,24.65) v5(6.98,12.91) v5(7.05,29.42) v5(7.13,28.93) v5(7.13,28.43) v5(7.13,27.93) v5(7.13,27.43) v5(7.13,26.93) v5(7.13,10.26) v5(7.17,29.81) v5(7.21,26.45) v5(7.23,24.38) v5(7.17,15.61) v5(7.2,1.81) v5(7.31,24.77) v5(7.26,16.46) v5(7.39,26.06) v5(7.42,14.72) v5(7.37,13.85) v5(7.6,31.59) v5(7.6,31) v5(7.65,25.73) v5(7.58,24.51) v5(7.58,18.32) v5(7.72,2.77) v5(7.77,16.53) v5(7.92,31.29) v5(7.92,30.89) v5(7.87,30.54) v5(7.94,25.44) v5(7.86,15.25) v5(7.86,14.49) v5(8.12,31.59) v5(8.11,30.1) v5(8.11,29.64) v5(8.11,29.14) v5(8.11,28.64) v5(8.11,28.14) v5(8.11,27.64) v5(8.11,27.14) v5(8.07,15.9) v5(8.2,30.62) v5(8.15,26.72) v5(8.22,25.15) v5(8.33,30.97) v5(8.31,26.36) v5(8.32,4.97) v5(8.37,31.31) v5(8.37,30.34) v5(8.43,24.3) v5(8.62,31.59) v5(8.63,31.11) v5(8.58,30.76) v5(8.57,26.08) v5(8.61,3.48) v5(8.79,2) v5(8.86,25.79) v5(9.12,29.51) v5(9.15,28.99) v5(9.1,28) v5(9.09,27.5) v5(9.11,27.02) v5(9.08,24.95) v5(9.17,28.54) v5(9.24,26.71) v5(9.3,30.01) v5(9.52,30.46) v5(9.5,29.61) v5(9.52,29.14) v5(9.5,26.42) v5(9.57,31.59) v5(9.57,31.01) v5(9.67,30.11) v5(9.74,16.09) v5(9.82,30.71) v5(9.76,25.6) v5(9.77,19.29) v5(9.87,31.31) v5(9.95,29.91) v5(9.9,29.56) v5(9.87,2.61) v5(9.89,2.17) v5(10.05,31.59) v5(10.02,1.68) v5(10.1,28.22) v5(10.06,27.73) v5(10.06,27.23) v5(10.22,31.29) v5(10.2,30.71) v5(10.27,30.28) v5(10.3,29.96) v5(10.4,28.66) v5(10.42,27.96) v5(10.4,27.46) v5(10.38,26.25) v5(10.55,31.59) v5(10.55,30.99) v5(10.55,30.44) v5(10.55,28.26) v5(10.48,2.74) v5(10.66,1.69) v5(10.8,29.01) v5(10.83,28.6) v5(10.9,2.21) v5(11.17,29.41) v5(11.25,29.01) v5(11.22,11.78) v5(11.18,2.74) v5(11.26,12.91) v5(11.25,1.74) v5(11.42,29.86) v5(11.52,31.59) v5(11.53,31.08) v5(11.55,30.66) v5(11.55,30.31) v5(11.56,29.48) v5(11.82,31.29) v5(11.83,29.98) v5(11.79,9.08) v5(11.87,31.59) v5(11.92,30.91) v5(11.92,30.46) v5(11.92,15.62) v5(11.97,9.72) v5(12.2,31.59) v5(12.23,31.26) v5(12.35,30.77) v5(12.45,9.71) v5(12.53,31.59) v5(12.55,31.09) v5(12.75,30.64) v5(12.67,30.26) v5(12.72,10.71) v5(12.86,11.78) v5(13.02,29.88) v5(12.97,1.38) v5(13.09,30.27) v5(13.21,29.08) v5(13.22,13.49) v5(13.44,29.92) v5(13.37,29.52) v5(13.37,6.67) v5(13.49,31.57) v5(13.48,11.38) v5(13.64,31.1) v5(13.66,13.05) v5(13.79,31.42) v5(13.79,29.56) v5(13.75,29.16) v5(13.98,31.12) v5(14,30.74) v5(14.07,31.59) v5(14.15,29.21) v5(14.09,28.79) v5(14.24,7.54) v5(14.24,6.64) v5(14.24,5.71) v5(14.3,31.24) v5(14.39,30.78) v5(14.35,30.39) v5(14.44,28.43) v5(14.55,31.59) v5(14.5,28.86) v5(14.75,31.24) v5(14.74,30.42) v5(14.7,30.04) v5(14.81,28.07) v5(14.85,28.5) v5(15,31.59) v5(15.09,30.07) v5(15.06,29.68) v5(15.21,28.15) v5(15.18,27.74) v5(15.27,31.23) v5(15.45,29.72) v5(15.41,29.33) v5(15.44,27.41) v5(15.42,26.21) v5(15.5,31.59) v5(15.56,27.79) v5(15.72,31.24) v5(15.68,27.15) v5(15.8,29.36) v5(15.76,28.97) v5(15.85,27.4) v5(15.97,31.59) v5(16.12,28.62) v5(16.06,25.57) v5(16.07,4.4) v5(16.2,31.29) v5(16.15,29.01) v5(16.33,26.48) v5(16.42,31.59) v5(16.44,14.28) v5(16.51,28.66) v5(16.47,28.27) v5(16.7,31.29) v5(16.68,26.82) v5(16.68,11.38) v5(16.75,27.83) v5(16.84,27.47) v5(16.92,31.59) v5(16.91,28.2) v5(17.04,27.71) v5(17.04,27.21) v5(17.02,25.81) v5(17.2,31.29) v5(17.32,27.59) v5(17.26,25.5) v5(17.4,31.59) v5(17.4,31.01) v5(17.41,30.58) v5(17.41,29.58) v5(17.41,29.08) v5(17.41,28.58) v5(17.39,28.08) v5(17.37,26.19) v5(17.5,25.76) v5(17.6,31.26) v5(17.75,31.59) v5(17.7,28.34) v5(17.72,27.91) v5(17.75,26.59) v5(17.77,30.81) v5(17.78,30.35) v5(17.78,29.85) v5(17.78,29.35) v5(17.78,28.85) v5(17.85,26.14) v5(17.97,31.24) v5(18.05,28.66) v5(18.1,31.59) v5(18.07,28.27) v5(18.1,26.96) v5(18.2,26.51) v5(18.35,29.04) v5(18.37,31.24) v5(18.42,28.62) v5(18.51,27.32) v5(18.55,26.86) v5(18.6,31.59) v5(18.72,29.41) v5(18.82,31.24) v5(18.78,28.97) v5(18.86,27.67) v5(18.95,27.24) v5(19.05,31.59) v5(19,25.24) v5(19.12,29.74) v5(19.14,29.32) v5(19.07,7.35) v5(19.21,28.03) v5(19.32,31.24) v5(19.32,27.61) v5(19.44,30.07) v5(19.55,31.59) v5(19.51,29.65) v5(19.57,28.38) v5(19.65,27.94) v5(19.73,30.4) v5(19.67,25.24) v5(19.8,31.24) v5(19.94,30.76) v5(19.85,29.99) v5(19.94,28.71) v5(20.02,31.59) v5(20.02,28.26) v5(20.08,31.08) v5(20.11,30.37) v5(20.28,30.77) v5(20.25,29.03) v5(20.37,31.59) v5(20.35,31.26) v5(20.38,28.61) v5(20.54,29.35) v5(20.51,8.42) v5(20.72,28.98) v5(20.69,7.33) v5(20.8,10.94) v5(20.85,29.73) v5(20.95,29.36) v5(21.1,30.17) v5(21.2,10.51) v5(21.33,31.58) v5(21.33,31.14) v5(21.26,30.64) v5(21.28,29.81) v5(21.28,21.41) v5(21.31,20.83) v5(21.41,8.42) v5(21.49,30.31) v5(21.5,20.15) v5(21.63,31.31) v5(21.62,30.84) v5(21.92,31.59) v5(22.15,31.24) v5(22.4,31.59) v5(22.6,31.24) v5(22.56,14.04) v5(22.83,31.58) v5(22.75,11.7) v5(22.77,10.61) v5(22.8,6.96) v5(23.1,31.24) v5(23.13,12.77) v5(23.21,31.59) v5(23.26,43.14) v5(23.26,42.7) v5(23.26,42.2) v5(23.26,41.75) v5(23.26,41.28) v5(23.26,40.8) v5(23.26,40.3) v5(23.26,39.85) v5(23.26,39.38) v5(23.26,38.9) v5(23.26,38.4) v5(23.26,37.95) v5(23.26,37.44) v5(23.26,36.97) v5(23.26,36.47) v5(23.26,36.02) v5(23.26,35.54) v5(23.26,35.07) v5(23.26,34.57) v5(23.26,34.12) v5(23.26,33.64) v5(23.26,33.17) v5(23.26,32.67) v5(23.26,32.22) v5(23.25,31.9) v5(23.38,19.48) v5(23.61,42.93) v5(23.61,42.45) v5(23.61,41.95) v5(23.61,41.5) v5(23.61,41.03) v5(23.61,40.55) v5(23.61,40.05) v5(23.61,39.6) v5(23.61,39.15) v5(23.61,38.68) v5(23.61,38.18) v5(23.61,37.73) v5(23.61,37.19) v5(23.61,36.72) v5(23.61,36.22) v5(23.61,35.77) v5(23.61,35.29) v5(23.61,34.82) v5(23.61,34.32) v5(23.63,33.87) v5(23.63,33.42) v5(23.61,32.94) v5(23.61,32.44) v5(23.61,31.99) v5(23.57,31.24) v5(23.69,31.59)
